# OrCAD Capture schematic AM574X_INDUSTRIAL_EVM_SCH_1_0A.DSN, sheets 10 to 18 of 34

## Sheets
10 Pg23: JTAG Debug: size C
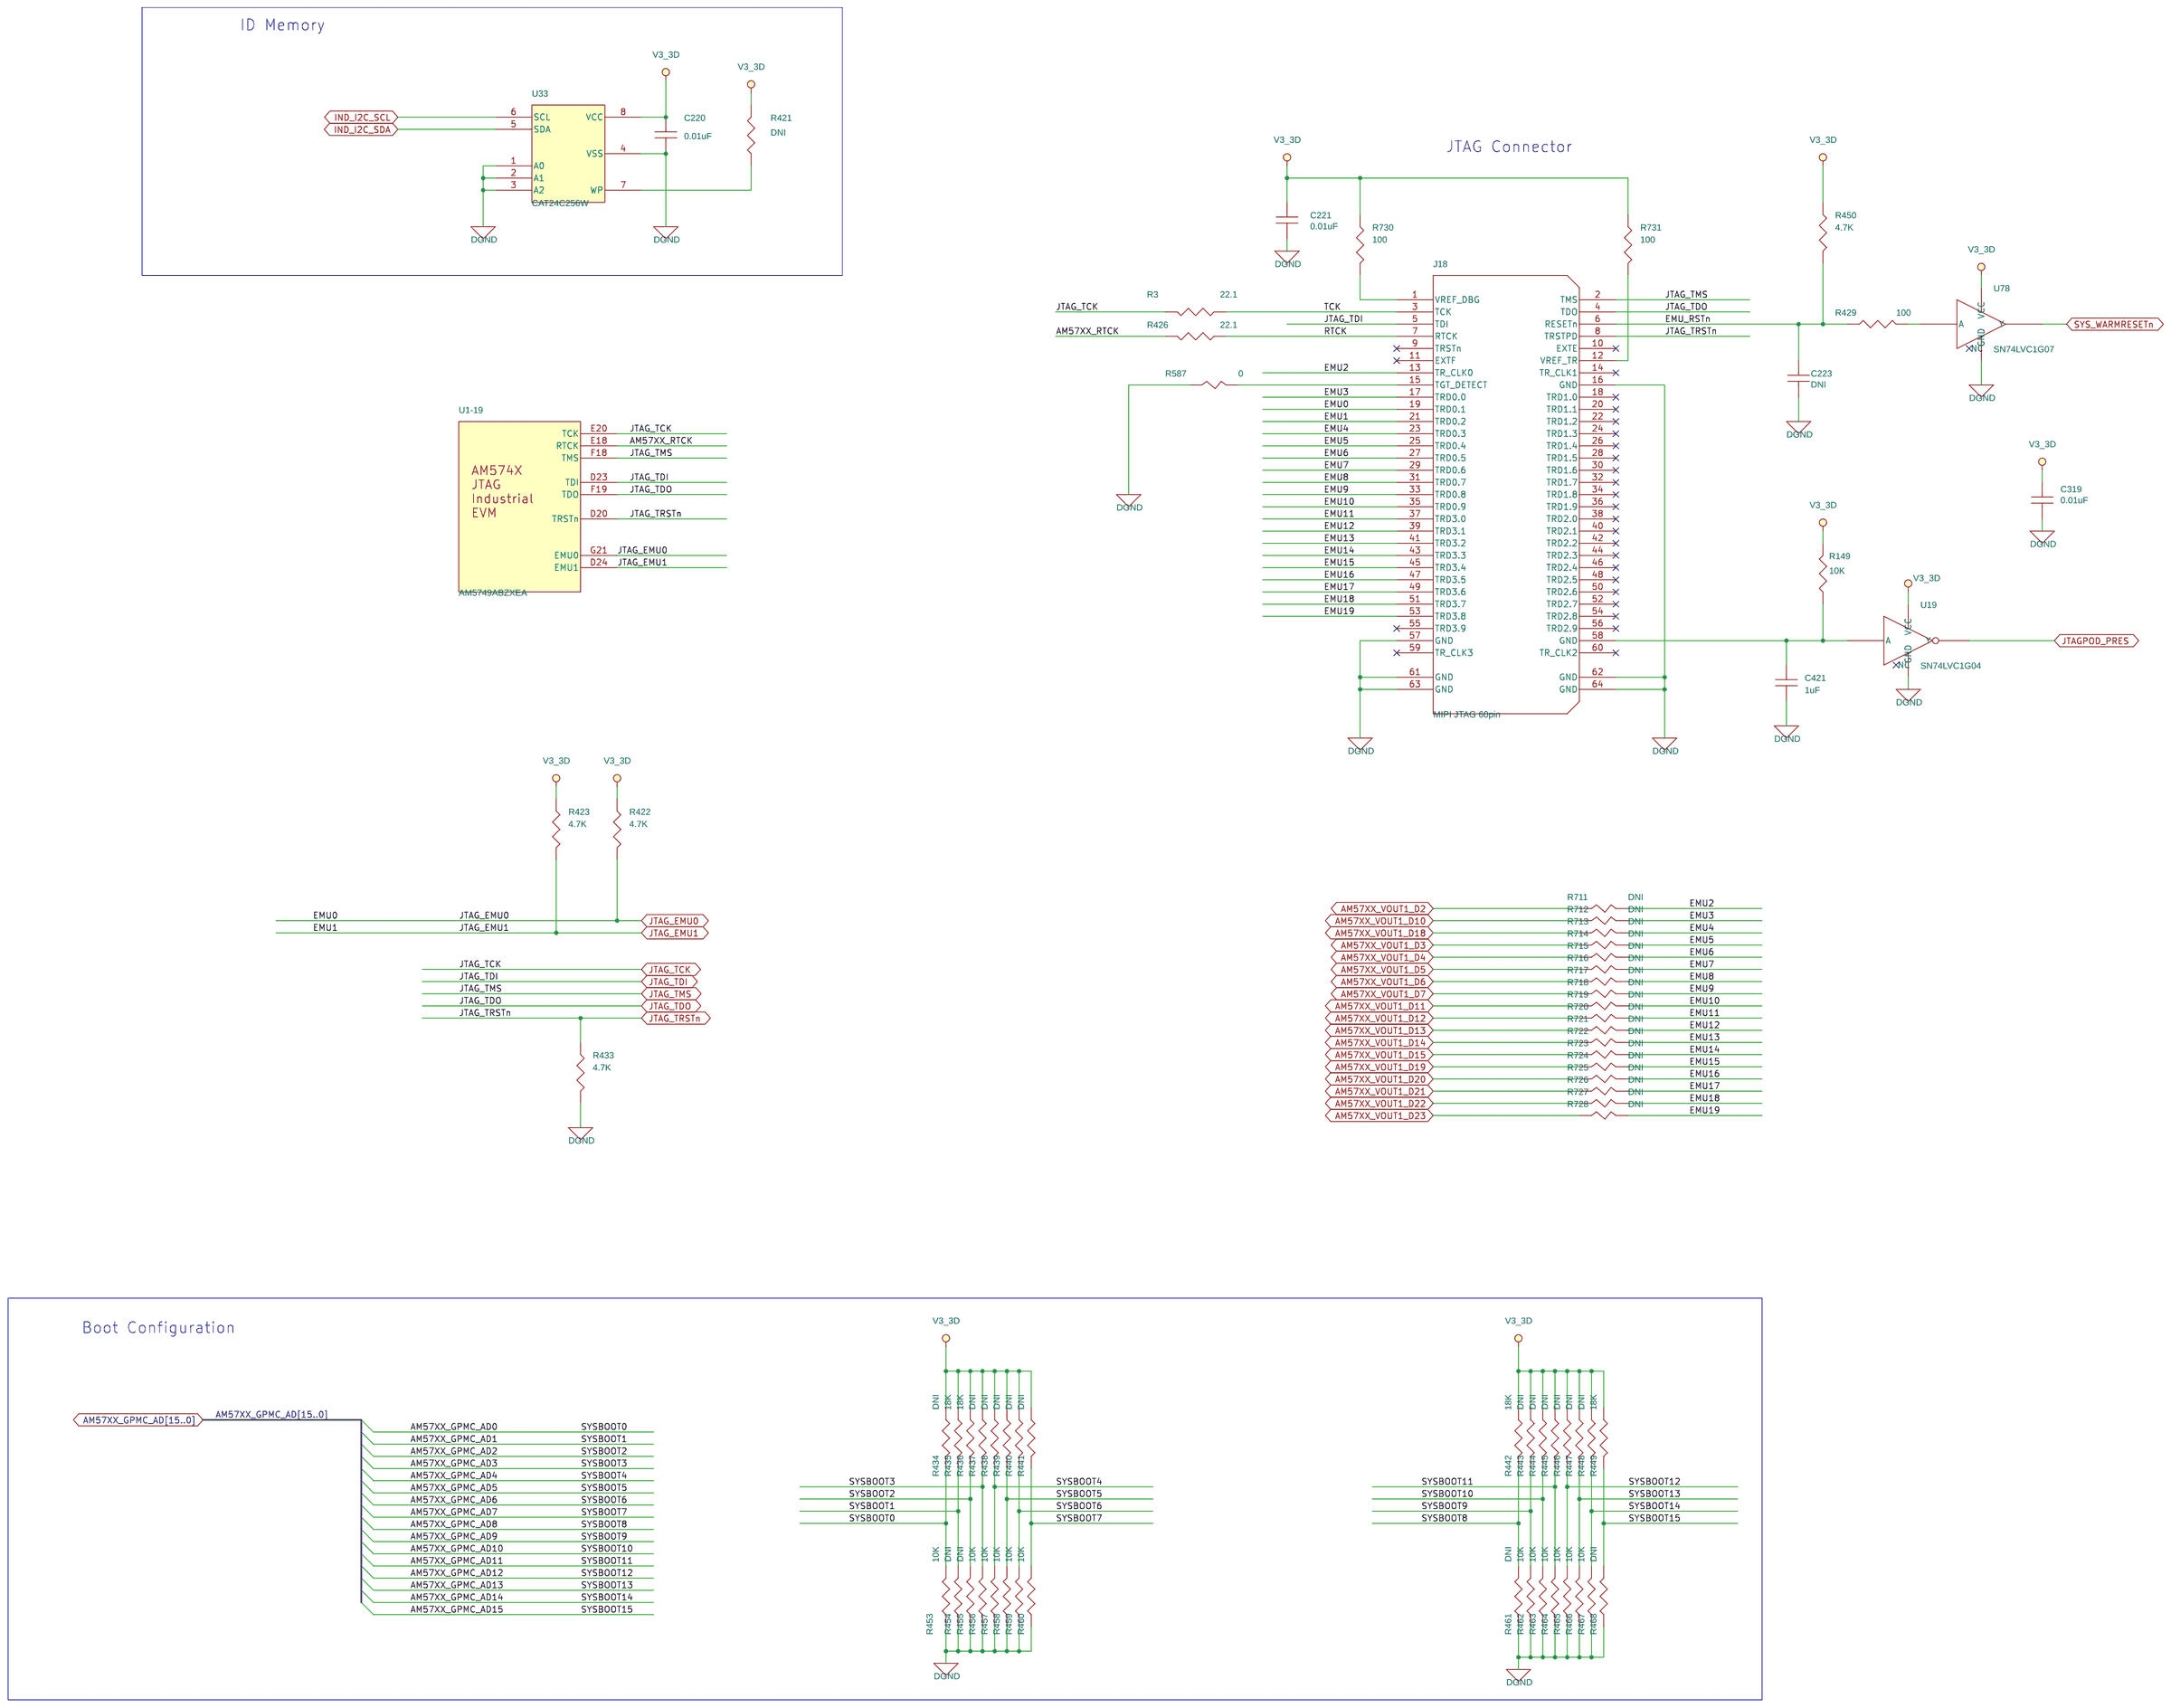
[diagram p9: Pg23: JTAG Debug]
11 Pg16: Camera #1: size C
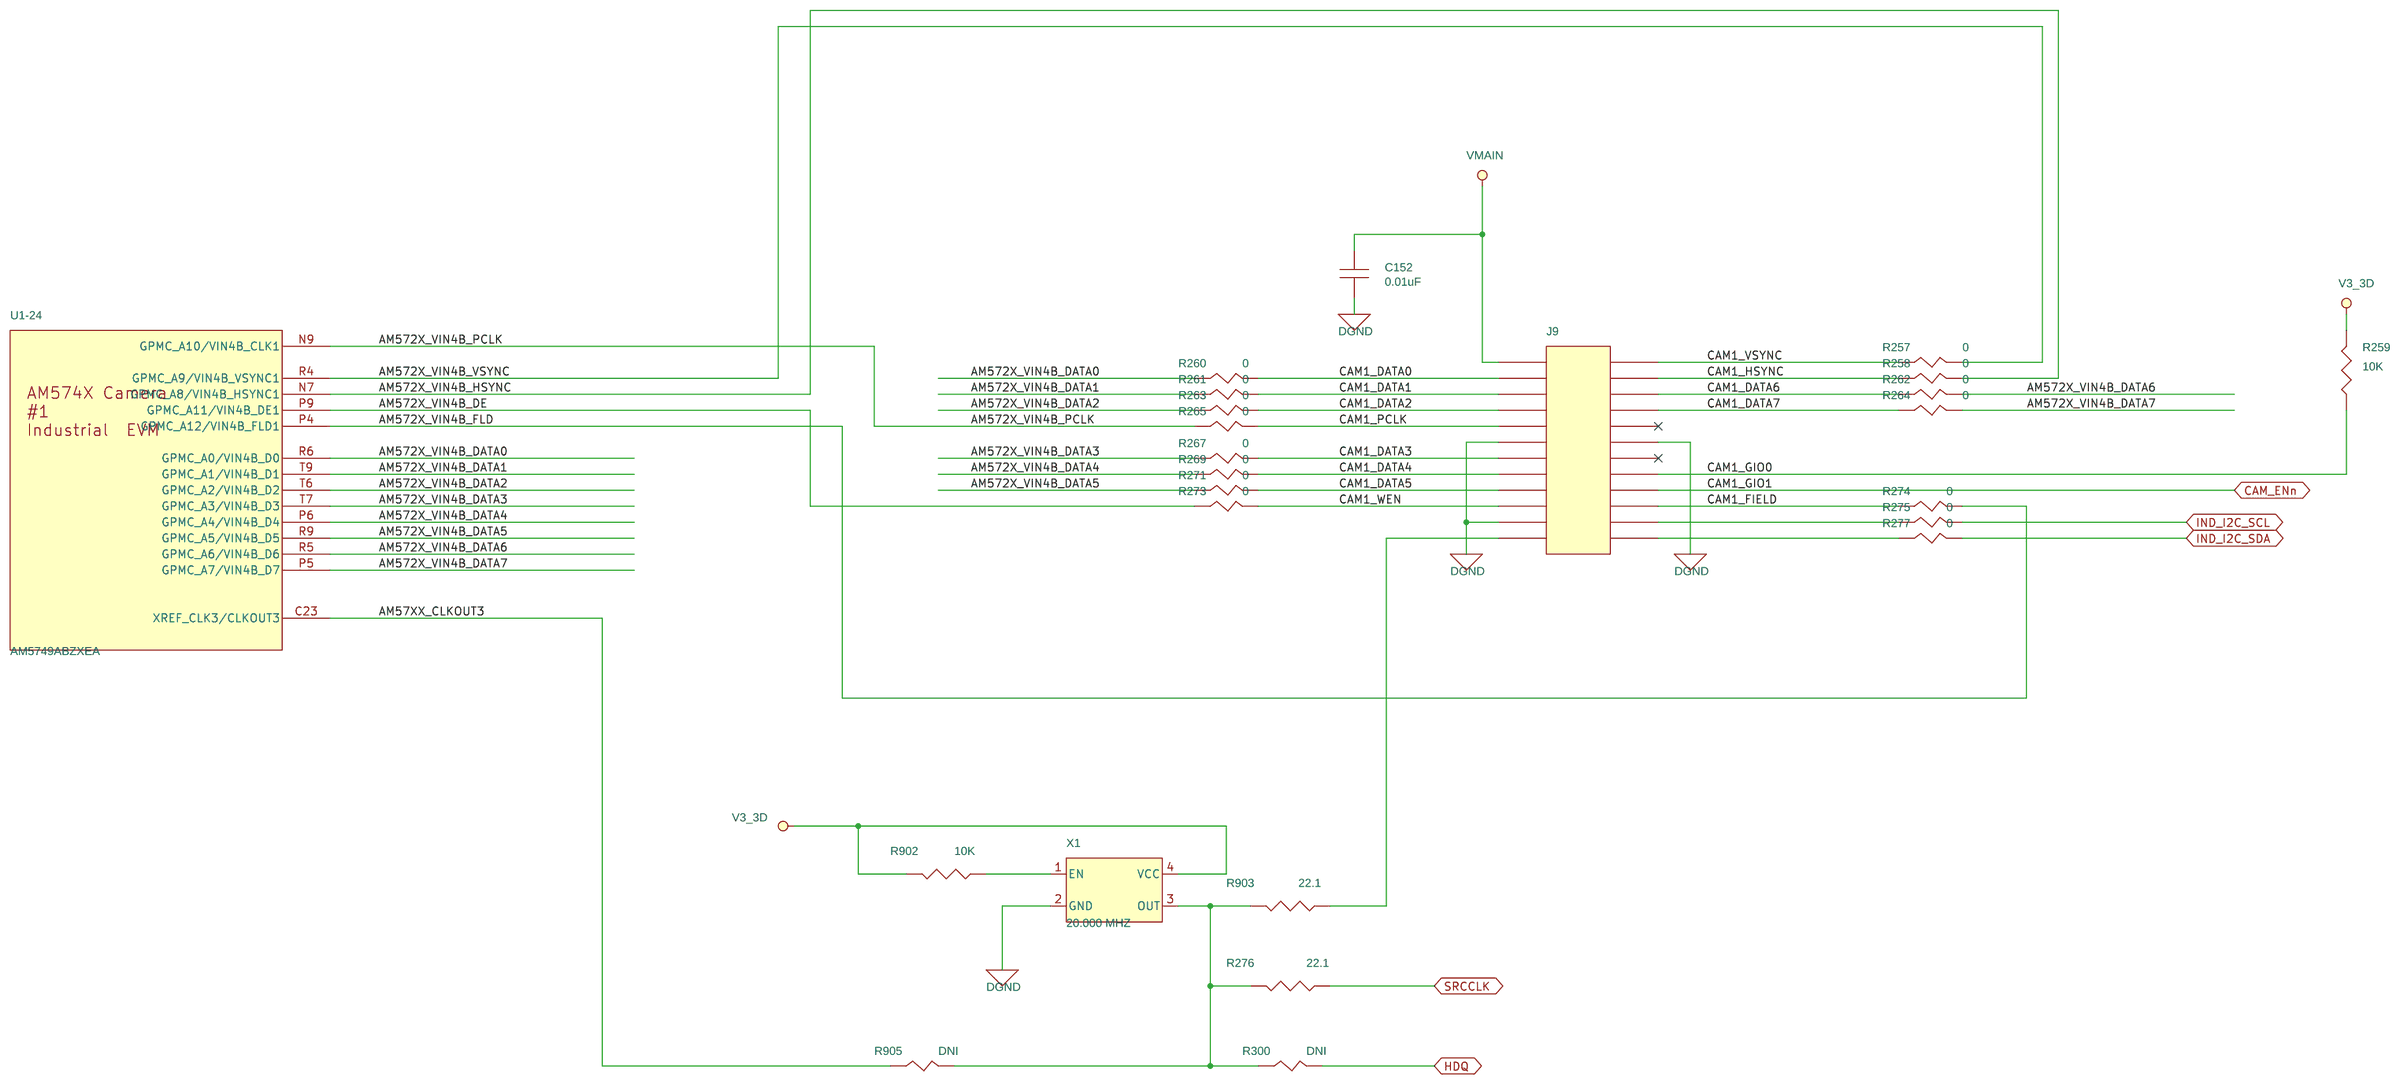
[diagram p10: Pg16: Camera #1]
12 Pg29: Profibus: size C
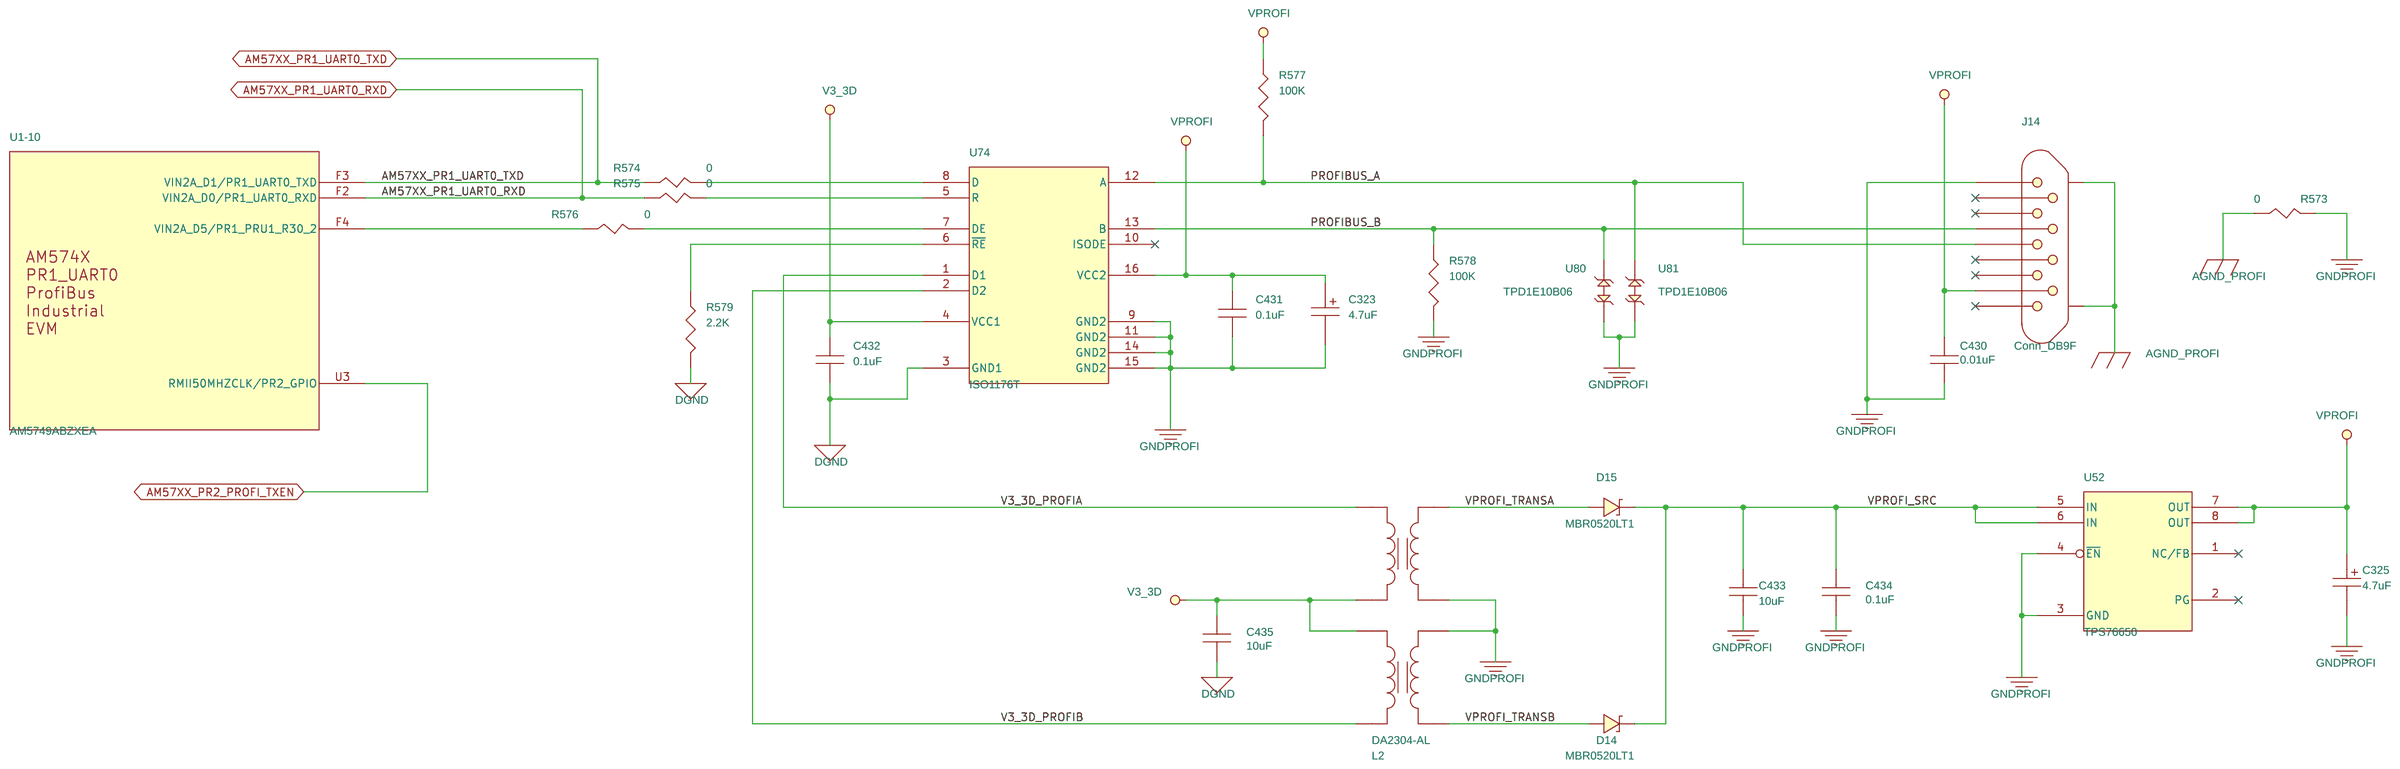
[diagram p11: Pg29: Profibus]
13 Pg01: Title Page
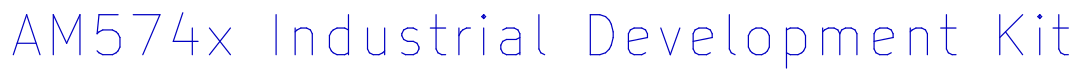
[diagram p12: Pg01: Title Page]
14 Pg27: USB #2 2.0: size C
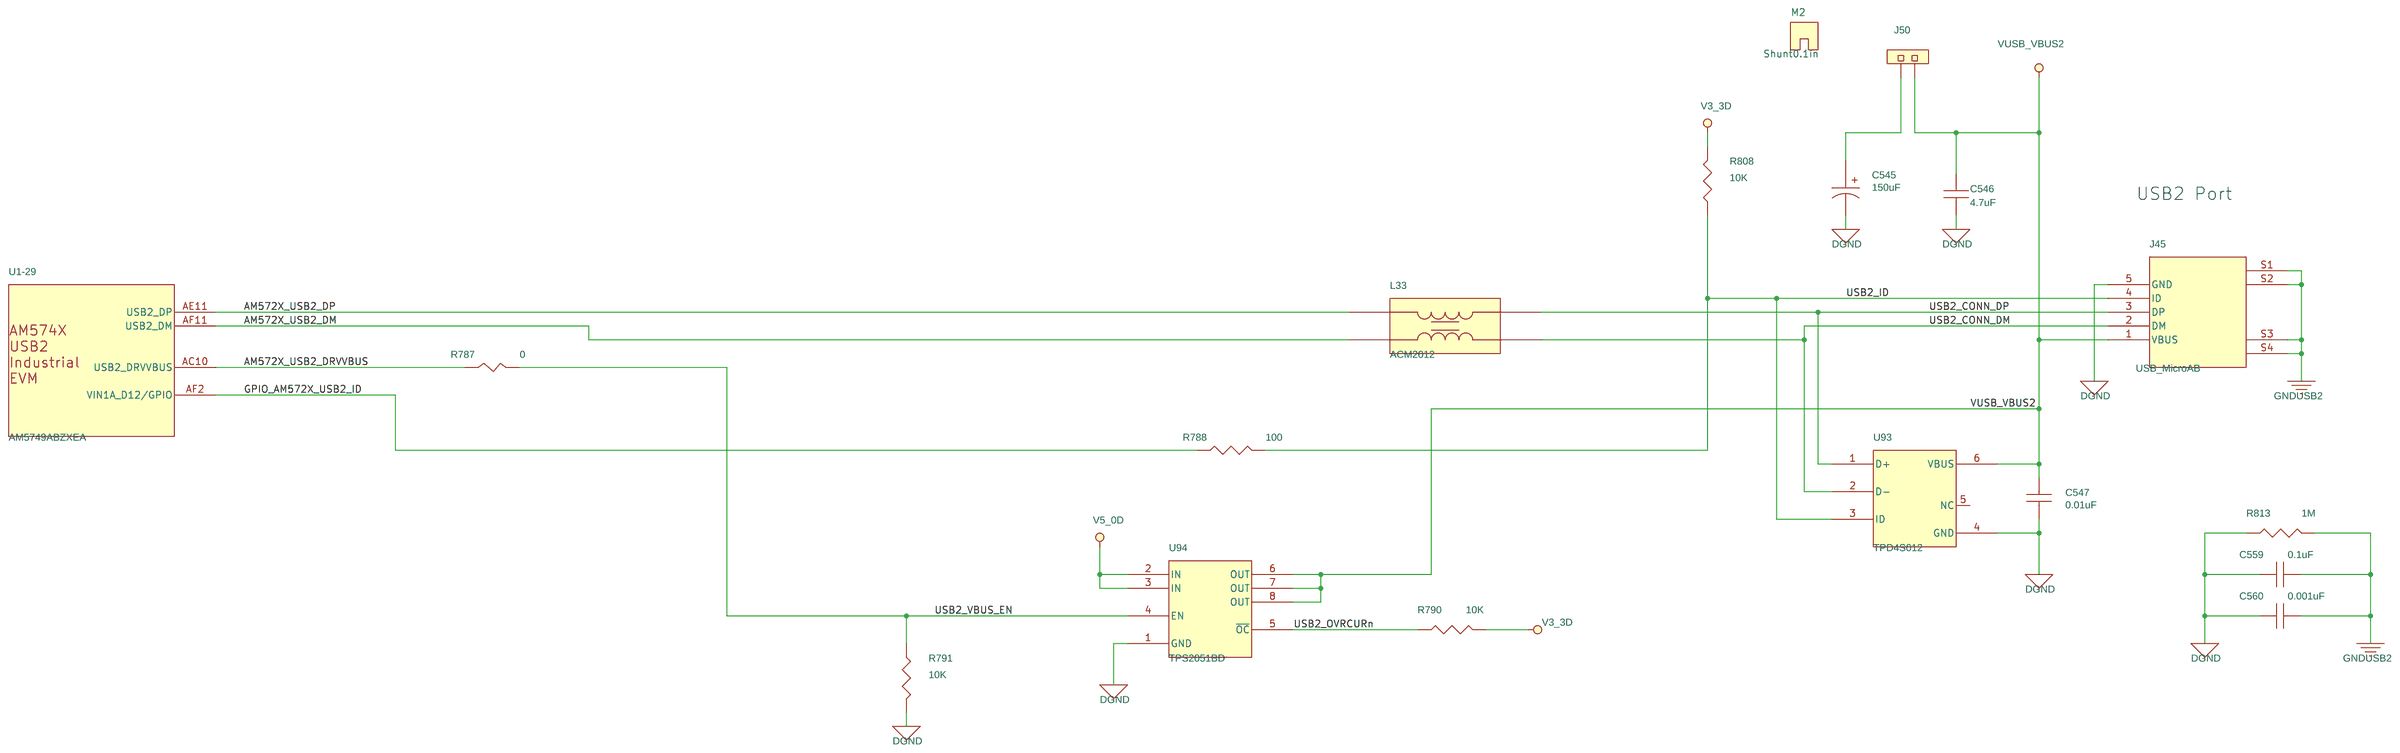
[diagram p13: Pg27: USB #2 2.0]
15 Pg26: USB #1 3.0: size C
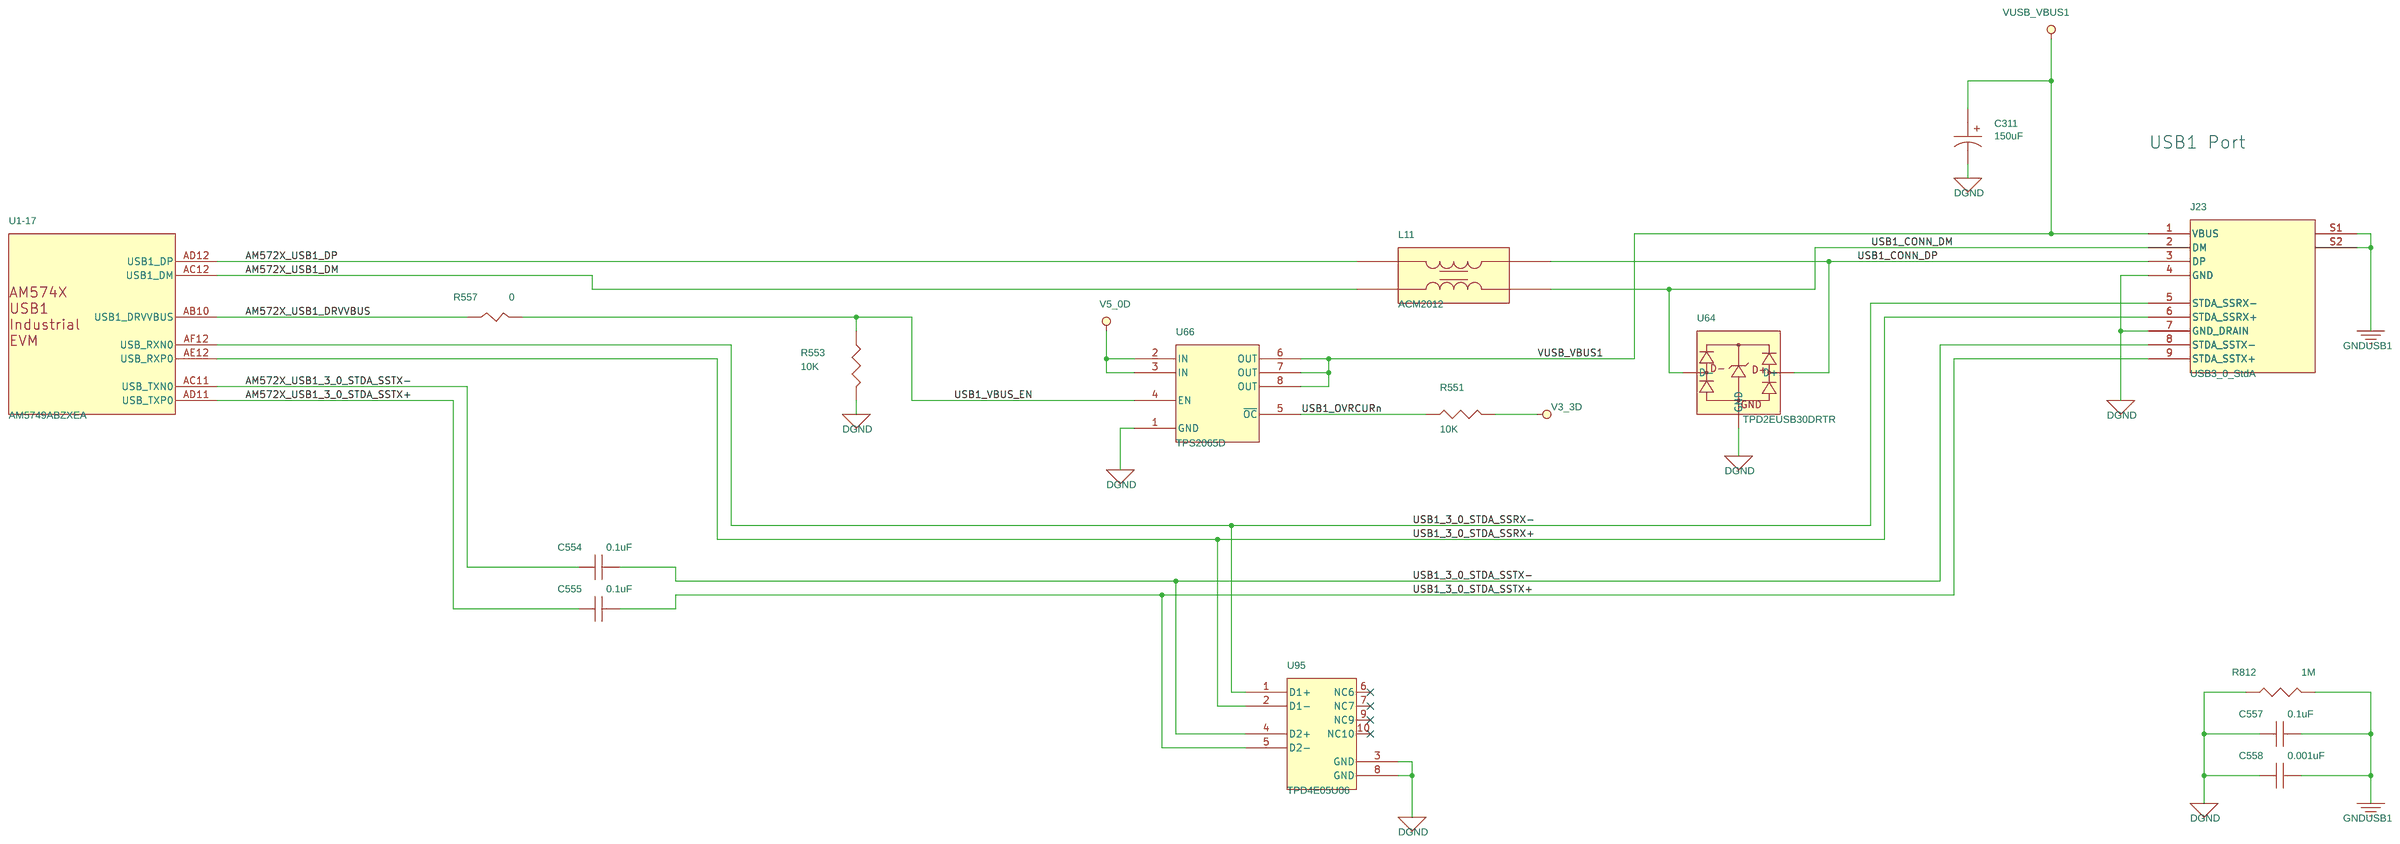
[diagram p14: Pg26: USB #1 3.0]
16 Pg08: DDR3 Memory 1: size C
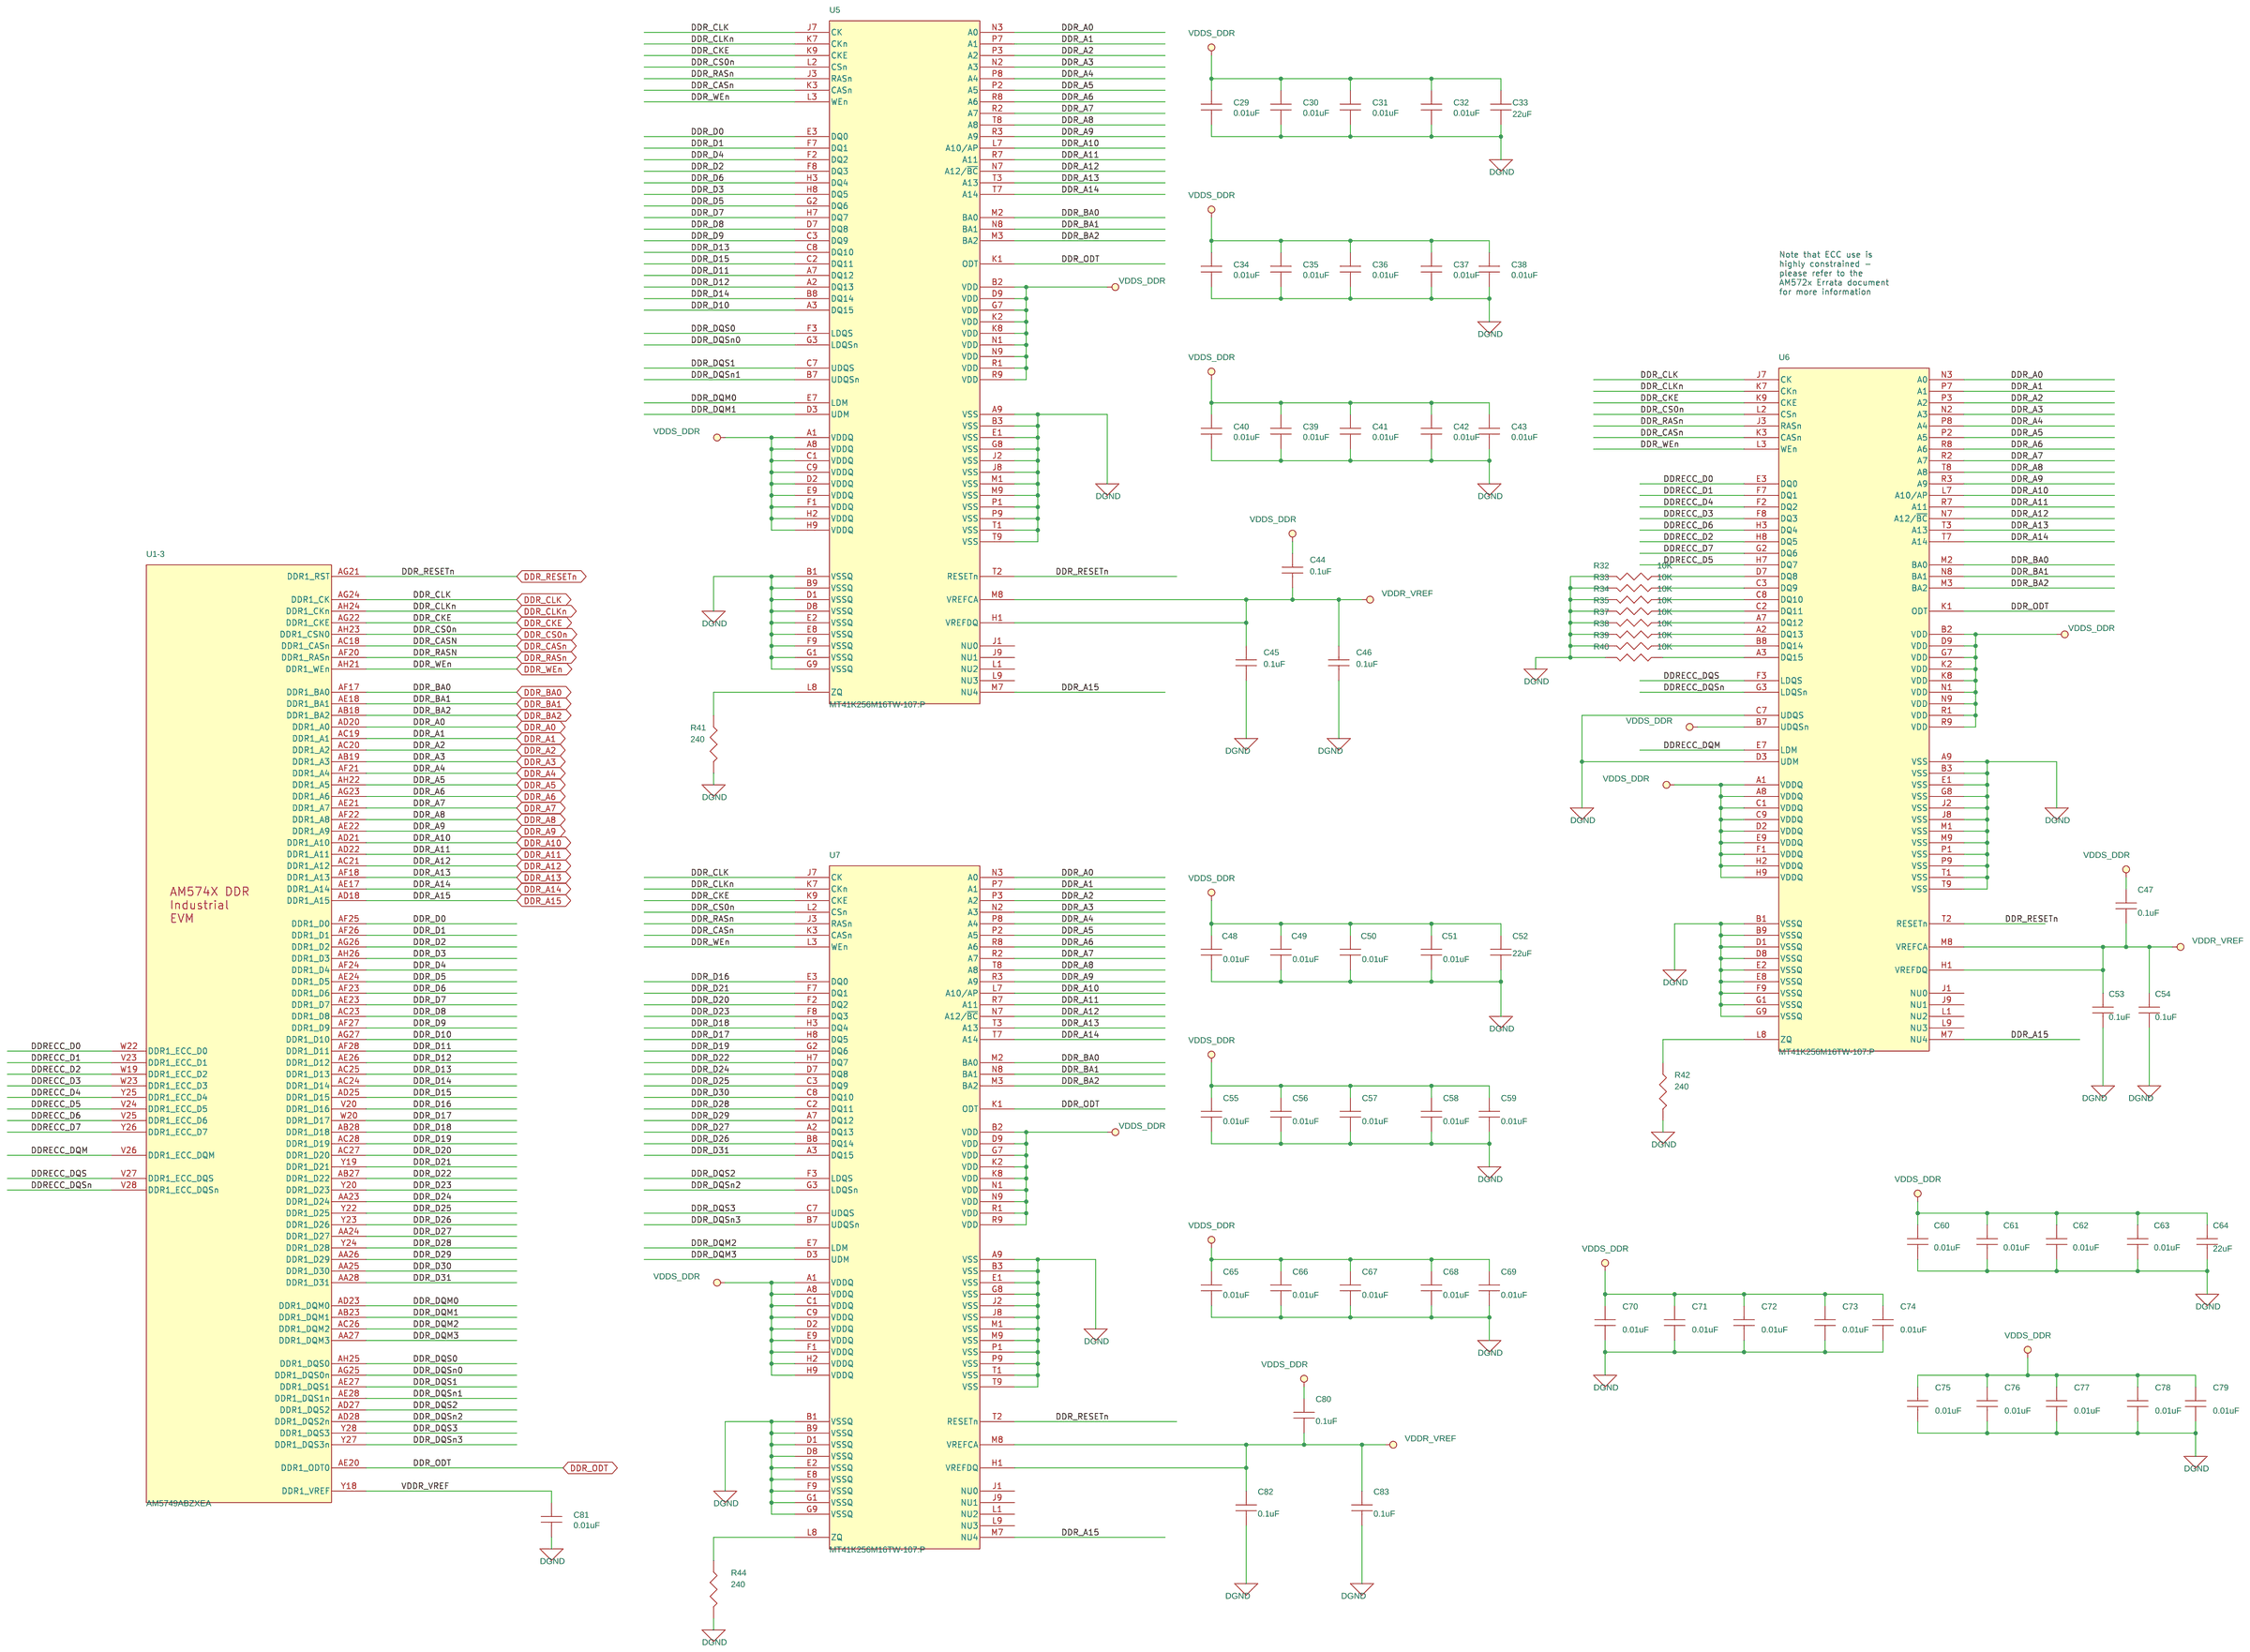
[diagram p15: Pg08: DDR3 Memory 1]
17 Pg13: ICSS2 Ethernet 0: size C
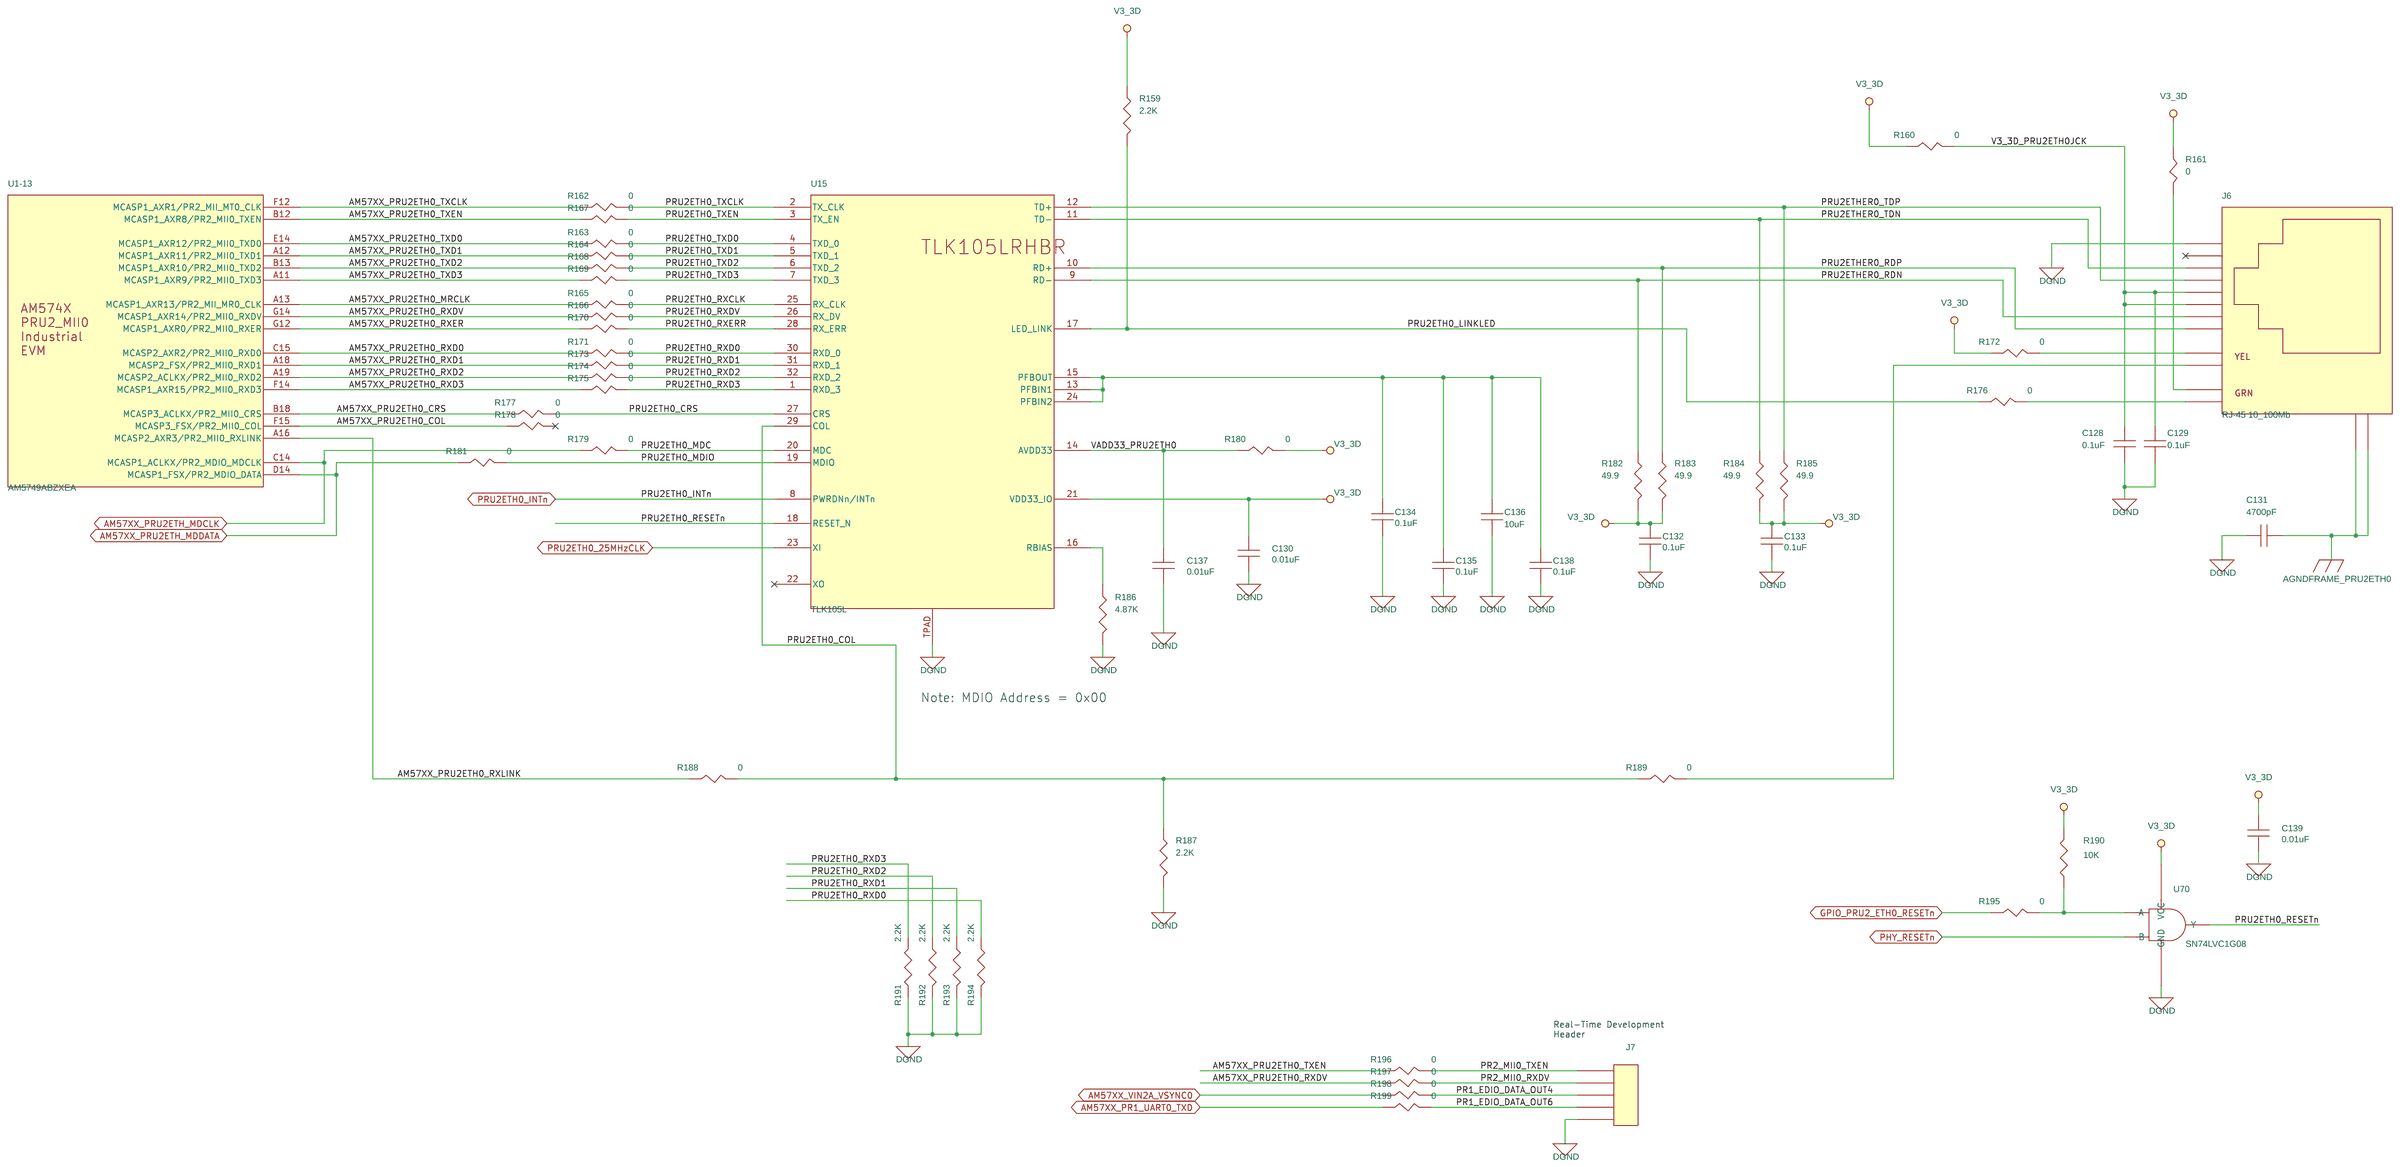
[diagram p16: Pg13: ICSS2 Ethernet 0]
18 Pg31: PCIE Connector: size C
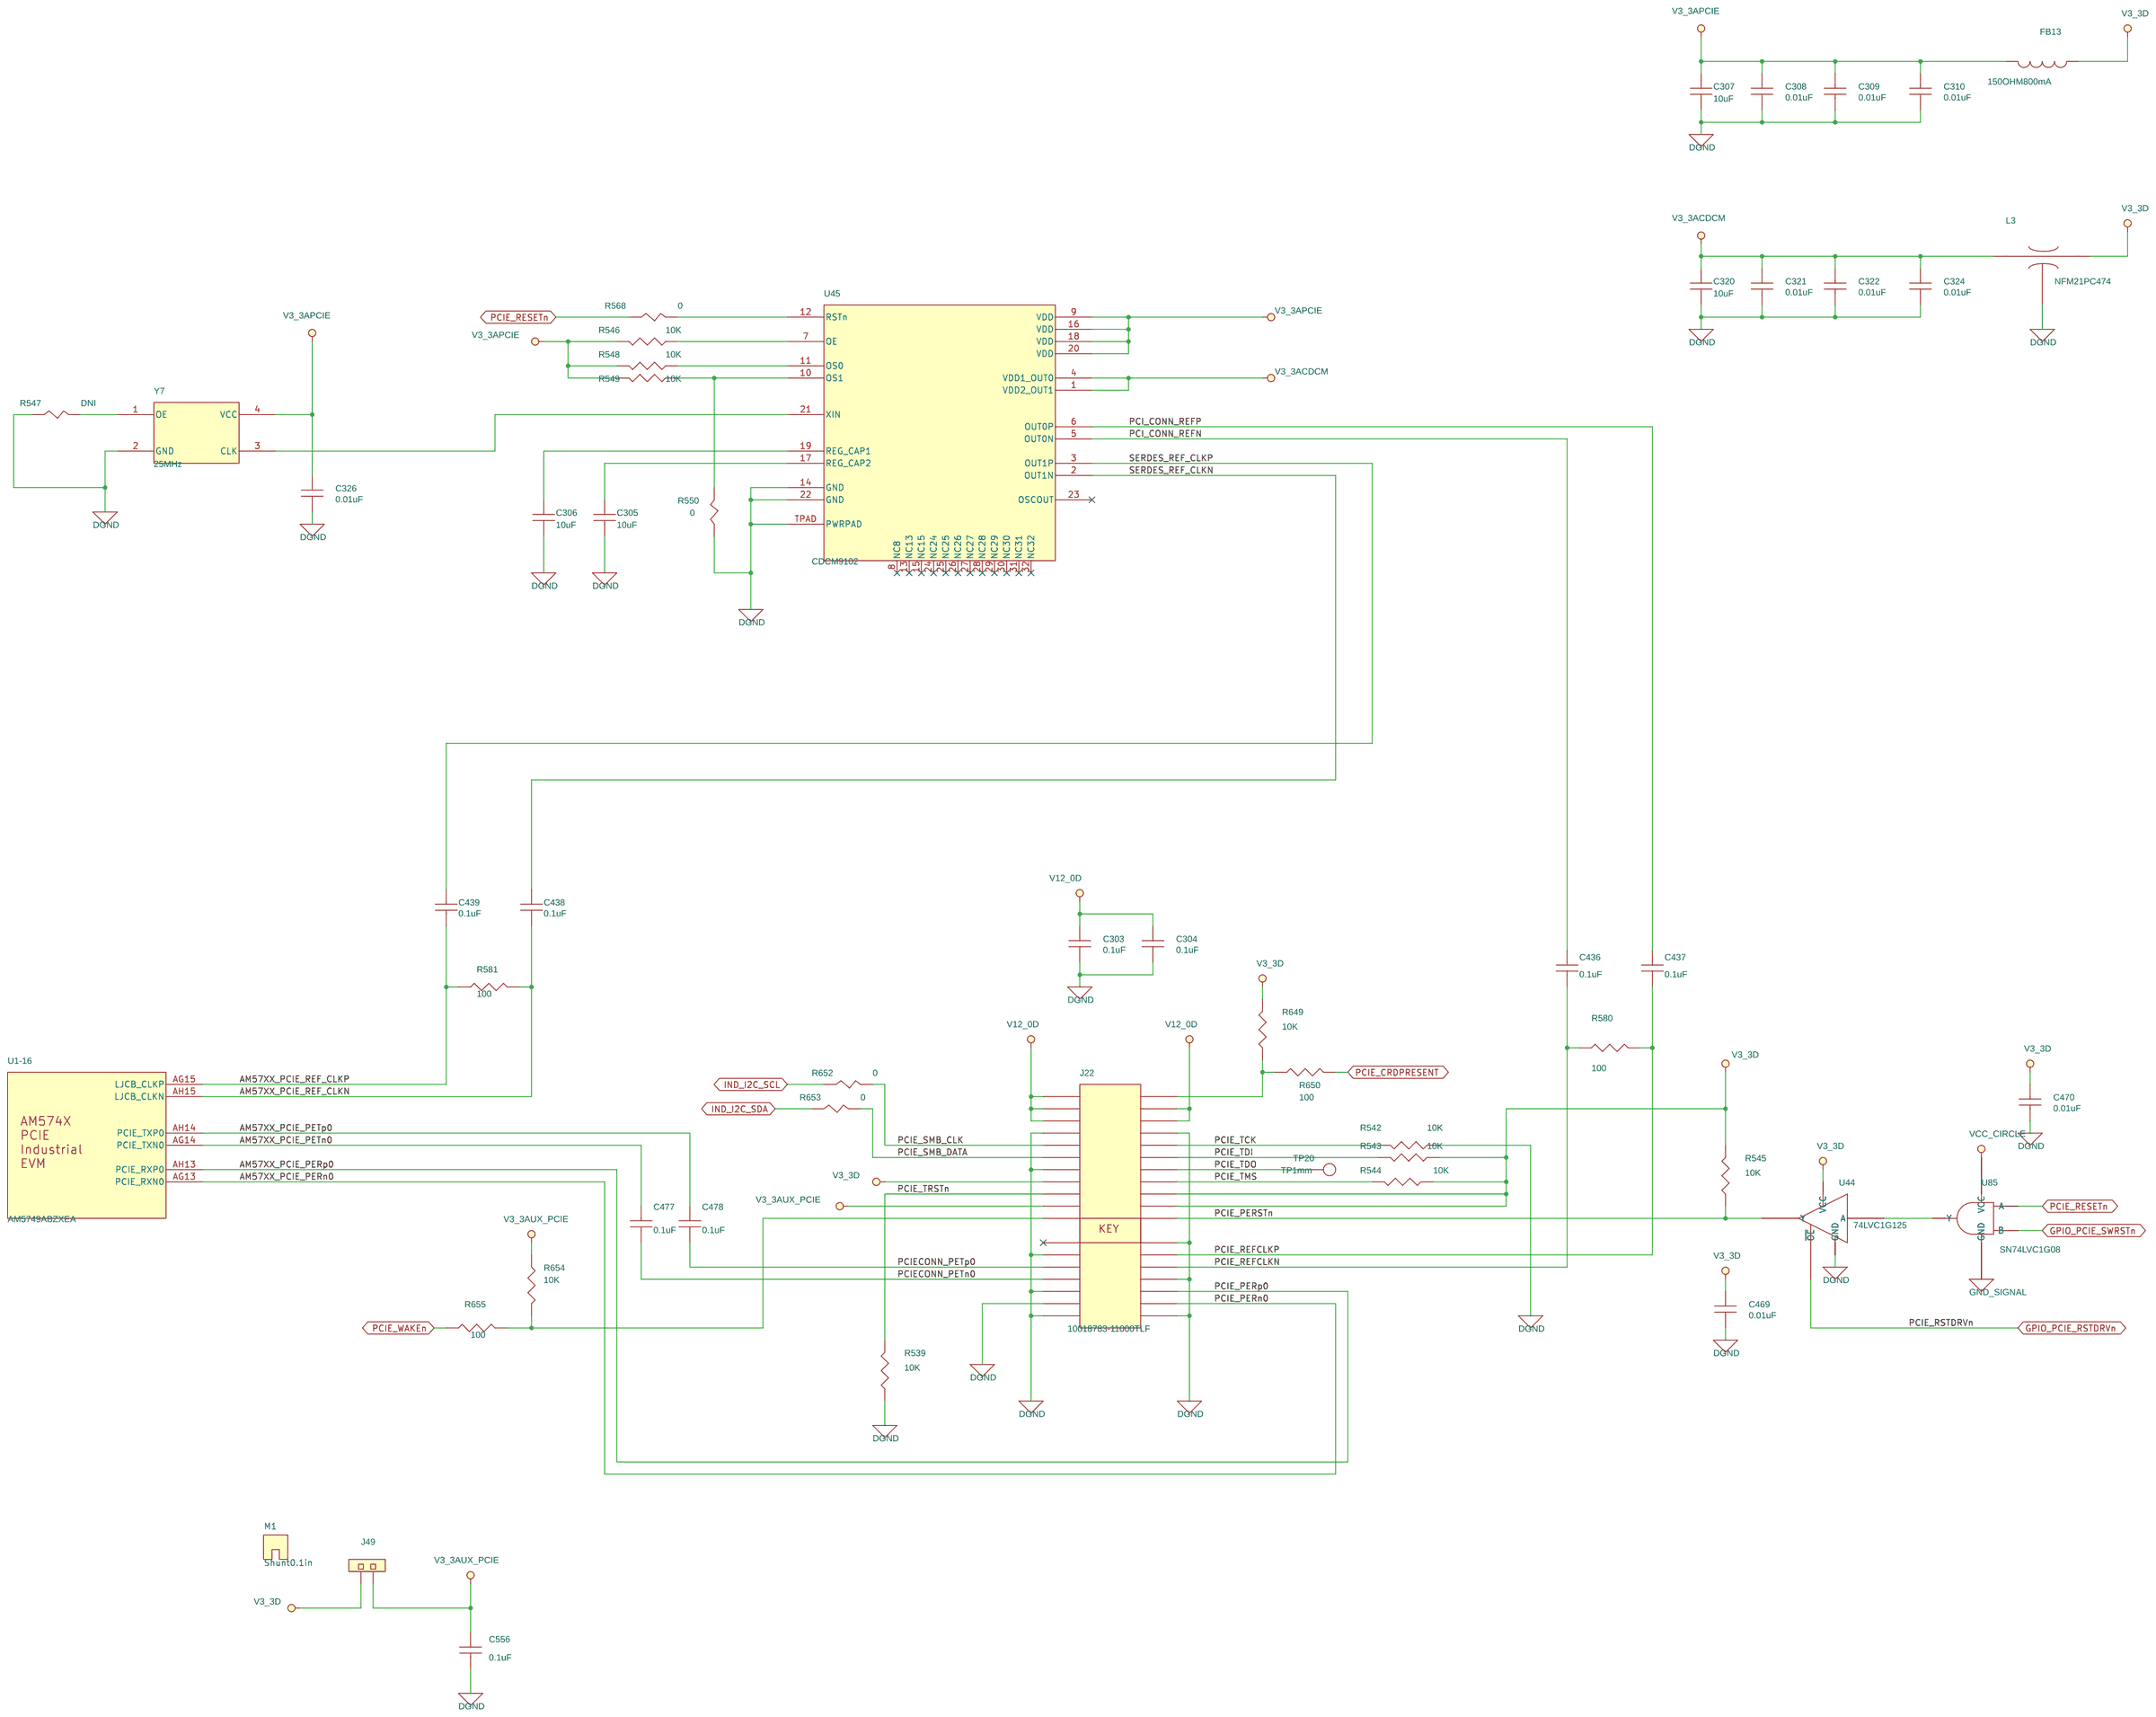
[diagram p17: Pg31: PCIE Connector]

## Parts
sheet Pg08: DDR3 Memory 1
C29  0.01uF  [SM-7351-CAP-0402]
C30  0.01uF  [SM-7351-CAP-0402]
C31  0.01uF  [SM-7351-CAP-0402]
C32  0.01uF  [SM-7351-CAP-0402]
C33  22uF  [SM-7351-CAP-0805]
C34  0.01uF  [SM-7351-CAP-0402]
C35  0.01uF  [SM-7351-CAP-0402]
C36  0.01uF  [SM-7351-CAP-0402]
C37  0.01uF  [SM-7351-CAP-0402]
C38  0.01uF  [SM-7351-CAP-0402]
C39  0.01uF  [SM-7351-CAP-0402]
C40  0.01uF  [SM-7351-CAP-0402]
C41  0.01uF  [SM-7351-CAP-0402]
C42  0.01uF  [SM-7351-CAP-0402]
C43  0.01uF  [SM-7351-CAP-0402]
C44  0.1uF  [SM-7351-CAP-0402]
C45  0.1uF  [SM-7351-CAP-0402]
C46  0.1uF  [SM-7351-CAP-0402]
C47  0.1uF  [SM-7351-CAP-0402]
C48  0.01uF  [SM-7351-CAP-0402]
C49  0.01uF  [SM-7351-CAP-0402]
C50  0.01uF  [SM-7351-CAP-0402]
C51  0.01uF  [SM-7351-CAP-0402]
C52  22uF  [SM-7351-CAP-0805]
C53  0.1uF  [SM-7351-CAP-0402]
C54  0.1uF  [SM-7351-CAP-0402]
C55  0.01uF  [SM-7351-CAP-0402]
C56  0.01uF  [SM-7351-CAP-0402]
C57  0.01uF  [SM-7351-CAP-0402]
C58  0.01uF  [SM-7351-CAP-0402]
C59  0.01uF  [SM-7351-CAP-0402]
C60  0.01uF  [SM-7351-CAP-0402]
C61  0.01uF  [SM-7351-CAP-0402]
C62  0.01uF  [SM-7351-CAP-0402]
C63  0.01uF  [SM-7351-CAP-0402]
C64  22uF  [SM-7351-CAP-0805]
C65  0.01uF  [SM-7351-CAP-0402]
C66  0.01uF  [SM-7351-CAP-0402]
C67  0.01uF  [SM-7351-CAP-0402]
C68  0.01uF  [SM-7351-CAP-0402]
C69  0.01uF  [SM-7351-CAP-0402]
C70  0.01uF  [SM-7351-CAP-0402]
C71  0.01uF  [SM-7351-CAP-0402]
C72  0.01uF  [SM-7351-CAP-0402]
C73  0.01uF  [SM-7351-CAP-0402]
C74  0.01uF  [SM-7351-CAP-0402]
C75  0.01uF  [SM-7351-CAP-0402]
C76  0.01uF  [SM-7351-CAP-0402]
C77  0.01uF  [SM-7351-CAP-0402]
C78  0.01uF  [SM-7351-CAP-0402]
C79  0.01uF  [SM-7351-CAP-0402]
C80  0.1uF  [SM-7351-CAP-0402]
C81  0.01uF  [SM-7351-CAP-0402]
C82  0.1uF  [SM-7351-CAP-0402]
C83  0.1uF  [SM-7351-CAP-0402]
R32  10K  [SM-7351-RES-0402]
R33  10K  [SM-7351-RES-0402]
R34  10K  [SM-7351-RES-0402]
R35  10K  [SM-7351-RES-0402]
R37  10K  [SM-7351-RES-0402]
R38  10K  [SM-7351-RES-0402]
R39  10K  [SM-7351-RES-0402]
R40  10K  [SM-7351-RES-0402]
R41  240  [sm-7351-res-0402]
R42  240  [sm-7351-res-0402]
R44  240  [sm-7351-res-0402]
U5  MT41K256M16TW-107:P  [bga9x14-96]
U6  MT41K256M16TW-107:P  [bga9x14-96]
U7  MT41K256M16TW-107:P  [bga9x14-96]
sheet Pg13: ICSS2 Ethernet 0
C128  0.1uF  [SM-7351-CAP-0402]
C129  0.1uF  [SM-7351-CAP-0402]
C130  0.01uF  [SM-7351-CAP-0402]
C131  4700pF  [SM-7351-CAP-0402]
C132  0.1uF  [SM-7351-CAP-0402]
C133  0.1uF  [SM-7351-CAP-0402]
C134  0.1uF  [SM-7351-CAP-0402]
C135  0.1uF  [SM-7351-CAP-0402]
C136  10uF  [SM-7351-CAP-0805]
C137  0.01uF  [SM-7351-CAP-0402]
C138  0.1uF  [SM-7351-CAP-0402]
C139  0.01uF  [SM-7351-CAP-0402]
J6  RJ-45 10_100Mb  [CNRJ45-1X1WLED]
J7  HEADER 5  [HEADER_5X1]
R159  2.2K  [sm-7351-res-0402]
R160  0  [SM-7351-RES-0402]
R161  0  [SM-7351-RES-0402]
R162  0  [SM-7351-RES-0402]
R163  0  [SM-7351-RES-0402]
R164  0  [SM-7351-RES-0402]
R165  0  [SM-7351-RES-0402]
R166  0  [SM-7351-RES-0402]
R167  0  [SM-7351-RES-0402]
R168  0  [SM-7351-RES-0402]
R169  0  [SM-7351-RES-0402]
R170  0  [SM-7351-RES-0402]
R171  0  [SM-7351-RES-0402]
R172  0  [SM-7351-RES-0402]
R173  0  [SM-7351-RES-0402]
R174  0  [SM-7351-RES-0402]
R175  0  [SM-7351-RES-0402]
R176  0  [SM-7351-RES-0402]
R177  0  [SM-7351-RES-0402]
R178  0  [SM-7351-RES-0402]
R179  0  [SM-7351-RES-0402]
R180  0  [SM-7351-RES-0603]
R181  0  [SM-7351-RES-0402]
R182  49.9  [SM-7351-RES-0402]
R183  49.9  [SM-7351-RES-0402]
R184  49.9  [SM-7351-RES-0402]
R185  49.9  [SM-7351-RES-0402]
R186  4.87K  [SM-7351-RES-0402]
R187  2.2K  [sm-7351-res-0402]
R188  0  [SM-7351-RES-0402]
R189  0  [SM-7351-RES-0402]
R190  10K  [SM-7351-RES-0402]
R191  2.2K  [sm-7351-res-0402]
R192  2.2K  [sm-7351-res-0402]
R193  2.2K  [sm-7351-res-0402]
R194  2.2K  [sm-7351-res-0402]
R195  0  [SM-7351-RES-0402]
R196  0  [SM-7351-RES-0402]
R197  0  [SM-7351-RES-0402]
R198  0  [SM-7351-RES-0402]
R199  0  [SM-7351-RES-0402]
U15  TLK105L  [qfn5x5-32-39m]
U70  SN74LVC1G08  [sm-so-sc70-5]
sheet Pg16: Camera #1
C152  0.01uF  [SM-7351-CAP-0402]
J9  HEADER 12x2  [hdr2x12]
R257  0  [SM-7351-RES-0402]
R258  0  [SM-7351-RES-0402]
R259  10K  [SM-7351-RES-0402]
R260  0  [SM-7351-RES-0402]
R261  0  [SM-7351-RES-0402]
R262  0  [SM-7351-RES-0402]
R263  0  [SM-7351-RES-0402]
R264  0  [SM-7351-RES-0402]
R265  0  [SM-7351-RES-0402]
R267  0  [SM-7351-RES-0402]
R269  0  [SM-7351-RES-0402]
R271  0  [SM-7351-RES-0402]
R273  0  [SM-7351-RES-0402]
R274  0  [SM-7351-RES-0402]
R275  0  [SM-7351-RES-0402]
R276  22.1  [SM-7351-RES-0402]
R277  0  [SM-7351-RES-0402]
R300  DNI  [SM-7351-RES-0402]
R902  10K  [SM-7351-RES-0402]
R903  22.1  [SM-7351-RES-0402]
R905  DNI  [SM-7351-RES-0402]
X1  20.000 MHZ  [OSC7X5-71M]
sheet Pg23: JTAG Debug
C220  0.01uF  [SM-7351-CAP-0402]
C221  0.01uF  [SM-7351-CAP-0402]
C223  DNI  [SM-7351-CAP-0402]
C319  0.01uF  [SM-7351-CAP-0402]
C421  1uF  [SM-7351-CAP-0603]
J18  MIPI JTAG 60pin  [CNQSH030DA]
R3  22.1  [SM-7351-RES-0402]
R149  10K  [SM-7351-RES-0402]
R421  DNI  [SM-7351-RES-0402]
R422  4.7K  [SM-7351-RES-0402]
R423  4.7K  [SM-7351-RES-0402]
R426  22.1  [SM-7351-RES-0402]
R429  100  [SM-7351-RES-0402]
R433  4.7K  [SM-7351-RES-0402]
R434  DNI  [SM-7351-RES-0402]
R435  18K  [SM-7351-RES-0402]
R436  18K  [SM-7351-RES-0402]
R437  DNI  [SM-7351-RES-0402]
R438  DNI  [SM-7351-RES-0402]
R439  DNI  [SM-7351-RES-0402]
R440  DNI  [SM-7351-RES-0402]
R441  DNI  [SM-7351-RES-0402]
R442  18K  [SM-7351-RES-0402]
R443  DNI  [SM-7351-RES-0402]
R444  DNI  [SM-7351-RES-0402]
R445  DNI  [SM-7351-RES-0402]
R446  DNI  [SM-7351-RES-0402]
R447  DNI  [SM-7351-RES-0402]
R448  DNI  [SM-7351-RES-0402]
R449  18K  [SM-7351-RES-0402]
R450  4.7K  [SM-7351-RES-0402]
R453  10K  [SM-7351-RES-0402]
R454  DNI  [SM-7351-RES-0402]
R455  DNI  [SM-7351-RES-0402]
R456  10K  [SM-7351-RES-0402]
R457  10K  [SM-7351-RES-0402]
R458  10K  [SM-7351-RES-0402]
R459  10K  [SM-7351-RES-0402]
R460  10K  [SM-7351-RES-0402]
R461  DNI  [SM-7351-RES-0402]
R462  10K  [SM-7351-RES-0402]
R463  10K  [SM-7351-RES-0402]
R464  10K  [SM-7351-RES-0402]
R465  10K  [SM-7351-RES-0402]
R466  10K  [SM-7351-RES-0402]
R467  10K  [SM-7351-RES-0402]
R468  DNI  [SM-7351-RES-0402]
R587  0  [SM-7351-RES-0402]
R711  DNI  [SM-7351-RES-0402]
R712  DNI  [SM-7351-RES-0402]
R713  DNI  [SM-7351-RES-0402]
R714  DNI  [SM-7351-RES-0402]
R715  DNI  [SM-7351-RES-0402]
R716  DNI  [SM-7351-RES-0402]
R717  DNI  [SM-7351-RES-0402]
R718  DNI  [SM-7351-RES-0402]
R719  DNI  [SM-7351-RES-0402]
R720  DNI  [SM-7351-RES-0402]
R721  DNI  [SM-7351-RES-0402]
R722  DNI  [SM-7351-RES-0402]
R723  DNI  [SM-7351-RES-0402]
R724  DNI  [SM-7351-RES-0402]
R725  DNI  [SM-7351-RES-0402]
R726  DNI  [SM-7351-RES-0402]
R727  DNI  [SM-7351-RES-0402]
R728  DNI  [SM-7351-RES-0402]
R730  100  [SM-7351-RES-0402]
R731  100  [SM-7351-RES-0402]
U19  SN74LVC1G04  [SC70-5-43M]
U33  CAT24C256W  [SOIC_8]
U78  SN74LVC1G07  [SC70-5-43M]
sheet Pg26: USB #1 3.0
C311  150uF  [SM-7351-CAP-2917]
C554  0.1uF  [SM-7351-CAP-0402]
C555  0.1uF  [SM-7351-CAP-0402]
C557  0.1uF  [SM-7351-CAP-0402]
C558  0.001uF  [SM-7351-CAP-0402]
J23  USB3_0_StdA  [cn_lpaf3102nl]
L11  ACM2012  [ACM2012H]
R551  10K  [SM-7351-RES-0402]
R553  10K  [SM-7351-RES-0402]
R557  0  [SM-7351-RES-0402]
R812  1M  [SM-7351-RES-0402]
U64  TPD2EUSB30DRTR  [SOT1X1-3-20M]
U66  TPS2065D  [U_8_D]
U95  TPD4E05U06  [USON2X1-10-22M]
sheet Pg27: USB #2 2.0
C545  150uF  [SM-7351-CAP-2917]
C546  4.7uF  [SM-7351-CAP-0603]
C547  0.01uF  [SM-7351-CAP-0402]
C559  0.1uF  [SM-7351-CAP-0402]
C560  0.001uF  [SM-7351-CAP-0402]
J45  USB_MicroAB  [ZX62-AB-5PA]
J50  HEADER 2  [header_2x1]
L33  ACM2012  [ACM2012H]
M2  Shunt0.1in  [none]
R787  0  [SM-7351-RES-0402]
R788  100  [SM-7351-RES-0402]
R790  10K  [SM-7351-RES-0402]
R791  10K  [SM-7351-RES-0402]
R808  10K  [SM-7351-RES-0402]
R813  1M  [SM-7351-RES-0402]
U93  TPD4S012  [U_6_DRY]
U94  TPS2051BD  [U_8_D]
sheet Pg29: Profibus
C323  4.7uF  [sm-7351-cap-0805]
C325  4.7uF  [sm-7351-cap-0805]
C430  0.01uF  [SM-7351-CAP-0402]
C431  0.1uF  [SM-7351-CAP-0402]
C432  0.1uF  [SM-7351-CAP-0402]
C433  10uF  [SM-7351-CAP-0805]
C434  0.1uF  [SM-7351-CAP-0402]
C435  10uF  [SM-7351-CAP-1206]
D14  MBR0520LT1  [mbr0520L]
D15  MBR0520LT1  [mbr0520L]
J14  Conn_DB9F  [NorComp_db9F_SMD]
L2  DA2304-AL  [DA2304]
R573  0  [SM-7351-RES-0402]
R574  0  [SM-7351-RES-0402]
R575  0  [SM-7351-RES-0402]
R576  0  [SM-7351-RES-0402]
R577  100K  [SM-7351-RES-0402]
R578  100K  [SM-7351-RES-0402]
R579  2.2K  [sm-7351-res-0402]
U1  AM5749ABZXEA  [BGA23X23-760-117M]  (sections -1,-10,-11,-12,-13,-14,-15,-16,-17,-18,-19,-2,-20,-21,-22,-23,-24,-25,-26,-27,-28,-29,-3,-4,-5,-6,-7,-8,-9)
U52  TPS76650  [soic_8]
U74  ISO1176T  [u_16_dw]
U80  TPD1E10B06  [tpd1e10b06-2l]
U81  TPD1E10B06  [tpd1e10b06-2l]
sheet Pg31: PCIE Connector
C303  0.1uF  [SM-7351-CAP-0402]
C304  0.1uF  [SM-7351-CAP-0402]
C305  10uF  [SM-7351-CAP-0805]
C306  10uF  [SM-7351-CAP-0805]
C307  10uF  [SM-7351-CAP-0805]
C308  0.01uF  [SM-7351-CAP-0402]
C309  0.01uF  [SM-7351-CAP-0402]
C310  0.01uF  [SM-7351-CAP-0402]
C320  10uF  [SM-7351-CAP-0805]
C321  0.01uF  [SM-7351-CAP-0402]
C322  0.01uF  [SM-7351-CAP-0402]
C324  0.01uF  [SM-7351-CAP-0402]
C326  0.01uF  [SM-7351-CAP-0402]
C436  0.1uF  [SM-7351-CAP-0402]
C437  0.1uF  [SM-7351-CAP-0402]
C438  0.1uF  [SM-7351-CAP-0402]
C439  0.1uF  [SM-7351-CAP-0402]
C469  0.01uF  [SM-7351-CAP-0402]
C470  0.01uF  [SM-7351-CAP-0402]
C477  0.1uF  [SM-7351-CAP-0402]
C478  0.1uF  [SM-7351-CAP-0402]
C556  0.1uF  [SM-7351-CAP-0402]
FB13  150OHM800mA  [sm-7351-ind-0805]
J22  10018783-11000TLF  [CN_10018783-11000TLF]
J49  HEADER 2  [header_2x1]
L3  NFM21PC474  [FILT-NFM21PC]
M1  Shunt0.1in  [none]
R539  10K  [SM-7351-RES-0402]
R542  10K  [SM-7351-RES-0402]
R543  10K  [SM-7351-RES-0402]
R544  10K  [SM-7351-RES-0402]
R545  10K  [SM-7351-RES-0402]
R546  10K  [SM-7351-RES-0402]
R547  DNI  [SM-7351-RES-0402]
R548  10K  [SM-7351-RES-0402]
R549  10K  [SM-7351-RES-0402]
R550  0  [SM-7351-RES-0402]
R568  0  [SM-7351-RES-0402]
R580  100  [SM-7351-RES-0402]
R581  100  [SM-7351-RES-0402]
R649  10K  [SM-7351-RES-0402]
R650  100  [SM-7351-RES-0402]
R652  0  [SM-7351-RES-0402]
R653  0  [SM-7351-RES-0402]
R654  10K  [SM-7351-RES-0402]
R655  100  [SM-7351-RES-0402]
TP20  TP1mm  [tp_smd1mmcircle]
U44  74LVC1G125  [SC70-5-43M]
U45  CDCM9102  [qfn5x5-32ti-39m]
U85  SN74LVC1G08  [sm-so-sc70-5]
Y7  25MHz  [asf_smd3_2x5mm]

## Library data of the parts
C29-C32 C34-C43 C48-C51 C55-C63 C65-C79 C81 C130 C137 C139 C152 C220 C221 C308-C310 C319 C321 C322 C324 C326 C430 C469 C470 C547 = 1C_0.01uFCapacitor16V10%0402
C33 C52 C64 = 1C_22uFCapacitor16V10%0805
C44-C47 C53 C54 C80 C82 C83 C128 C129 C132-C135 C138 C223 C436-C439 C477 C478 C554 C555 C557 C559 = C0402C104J4RACTU: DescriptiveText: CAP, CER, 0.1 uF, 16V, 5%, X7R, 0402; Mfr: KEMET
R32-R35 R37-R40 R149 R190 R259 R421 R453-R468 R539 R542-R546 R548 R549 R551 R553 R649 R654 R790 R791 R808 R902 = RMCF0402FT10K0: DescriptiveText: RES, THICK FILM,10K OHM, 1%, 0.063W, SMT0402; Mfr: STACKPOLE ELECTRONICS
R41 R42 R44 = 1R_240OhmResistor1_16W0402
U5-U7 = MT41K256M16HA-107
C131 = 1C_4700pFCapacitor50V10%0402
C136 C305-C307 C320 C433 = 1C_10uFCapacitor16V10%0805
J6 = 2J_ConnectorRJ45_10_100MbAMDIX
J7 = 2H_Header_5x1
R159 R187 R191-R194 R579 = 1R_2.2KOhmResistor1_16W0402
R160-R179 R181 R188 R189 R195-R199 R257 R258 R260-R265 R267 R269 R271 R273-R275 R277 R300 R547 R550 R557 R568 R573-R576 R587 R652 R653 R711-R728 R787 R905 = 1R_ZeroOhmResistor1_16W0402
R180 = 1R_ZeroOhmResistor1_16W0603
R182-R185 = 1R_49.9OhmResistor1_16W0402
R186 = 1R_4.87Kohm1_16W1%smd0402
U15 = TLK105LRHBR
U70 U85 = SN74LVC1G08DCKR
J9 = 2H_Header12x2
R3 R276 R426 R903 = RMCF0402FT22R1: DescriptiveText: RES, THICK FILM, 22.1 OHM, 1%, 0.063W, SMT0402; Mfr: STACKPOLE ELECTRONICS
X1 = CB3LV-3C-20M0000: DescriptiveText: OSC, XO, 20.000MHZ, HCMOS, TTL, SMD-4P; Mfr: CTS-Frequency Controls
C421 = 1C_1uFCapacitor50V10%0603
J18 = 2C_Conn_JTAGMIPI_60pin
R422 R423 R433 R450 = 1R_4.7KOhmResistor1_16W0402
R429 R580 R581 R650 R655 R788 = 1R_100ohm1_16W1%SMD0402: Cost100: 0.02; DescriptiveText: Resistor 100ohm 1/10W 1% 0402; Mfr: Panasonic; MfrNum: ERJ-2RKF1000X; PartName: 100ohm1/10W1%0402; TIIntPartnumber: 1R0246
R434-R449 = 1R_18KohmResistor1_10W1%smd0402
R730 R731 = 1R_100ohm1_10W1%SMD0402: DescriptiveText: Resistor 100ohm 1/10W 1% 0402; PartName: 100ohm1/10W1%0402
U19 = SN74LVC1G04DCKRE4
U33 = 1A_CAT24C256W
U78 = SN74LVC1G07DCKRE4
C311 C545 = T495D157K010ATE100: DescriptiveText: CAP, TANT, 150UF, 10V, 10%, 7343; Mfr: KEMET
C558 C560 = 1C_0.001uFCapacitor50V5%0402
J23 = 1932258-1
L11 L33 = ACM2012H-900-2P-T05
R812 R813 = 1R_1MOhmResistor1_16W0402
U64 = TPD2EUSB30DRTR: DescriptiveText: 2, 4-CHANNEL ESD SOLUTION FOR SUPER-SPEED (6 GBPS) USB 3.0 INTERFACE; Mfr: TEXAS INSTRUMENTS
U66 = 1A_TPS2065D
U95 = TPD4E05U06DQAR
C546 = 1C_4.7uFCapacitor16V10%0603
J45 = USB
J49 J50 = 2H_Header_0
M1 M2 = 2H_Shunt0.1in
U93 = TPD4S012DRYR
U94 = 1A_TPS2051BD
C323 C325 = 4.7uFCapacitor16V20%Tant
C303 C304 C431 C432 C434 C556 = C1005X7R1H104K050BE: DescriptiveText: CAP, CER, 0.1UF, 50V, 10%, X7R, 0402; Mfr: TDK CORPORATION
C435 = C3216X5R1H106K160AB: DescriptiveText: CAP, CER, 10 UF, 10%, 50V,  X5R, 1206, SMD; Mfr: TDK
D14 D15 = Diode_500mA20V: TIIntPartnumber: _1E0007
J14 = 2C_Conn_DSUB9F
L2 = DA2304-ALB
R577 R578 = 1R_100KOhmResistor1_16W0402
U1 = AM5749ABZXEA: DescriptiveText: Dual Cortex A15 Dual C66X SOC AM574x
U52 = TPS76650
U74 = 1A_ISO1176T
U80 U81 = TPD1E10B06DPYR
FB13 = 1L_FerBead_0
J22 = 2C_PCIEConnector_10018783
L3 = 1L_NFM21PC474_EMIFilter_0
TP20 = 2H_Testpoint_SMD1mmCircle
U44 = SN74LVC1G125DCKR
U45 = CDCM9102RHBT
Y7 = 1Y_Oscillator25MHzSMD

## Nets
AGND_PROFI: J14.10 J14.11 R573.2(P2)
AGNDFRAME_PRU2ETH0: C131.2 J6.SHLD1 J6.SHLD2
DGND: C29.2 C30.2 C31.2 C32.2 C33.2 C34.2 C35.2 C36.2 C37.2 C38.2 C39.2 C40.2 C41.2 C42.2 C43.2 C45.2 C46.2 C48.2 C49.2 C50.2 C51.2 C52.2 C53.2 C54.2 C55.2 C56.2 C57.2 C58.2 C59.2 C60.2 C61.2 C62.2 C63.2 C64.2 C65.2 C66.2 C67.2 C68.2 C69.2 C70.2 C71.2 C72.2 C73.2 C74.2 C75.2 C76.2 C77.2 C78.2 C79.2 C81.2 C82.2 C83.2 C128.2 C129.2 C130.2 C131.1 C132.2 C133.2 C134.2 C135.2 C136.2 C137.2 C138.2 C139.2 C152.2 C220.2 C221.2 C223.2 C303.2 C304.2 C305.2 C306.2 C307.2 C308.2 C309.2 C310.2 C311.2 C319.2 C320.2 C321.2 C322.2 C324.2 C326.2 C421.2 C432.2 C435.2 C469.2 C470.2 C545.2 C546.2 C547.2 C556.2 C557.1 C558.1 C559.1 C560.1 J6.8 J7.5 J9.11 J9.12 J9.21 J18.16(GND) J18.57(GND) J18.61(GND) J18.62(GND) J18.63(GND) J18.64(GND) J22.A4 J22.A12 J22.A15 J22.A18 J22.B4 J22.B7 J22.B13 J22.B16 J22.B17 J22.B18 J23.4(GND) J23.7(GND_DRAIN) J45.5(GND) L3.2(GND) R32.2 R33.2 R34.2 R35.2 R37.2 R38.2 R39.2 R40.2 R41.1(P1) R42.1(P1) R44.1(P1) R186.1(P1) R187.1(P1) R191.1(P1) R192.1(P1) R193.1(P1) R194.1(P1) R433.1(P1) R453.1 R454.1 R455.1 R456.1 R457.1 R458.1 R459.1 R460.1 R461.1 R462.1 R463.1 R464.1 R465.1 R466.1 R467.1 R468.1 R539.1 R542.1 R547.2(P2) R550.2(P2) R553.2 R579.1(P1) R587.2(P2) R791.2 R812.2(P2) R813.2(P2) U5.A9(VSS) U5.B1(VSSQ) U5.B3(VSS) U5.B9(VSSQ) U5.D1(VSSQ) U5.D8(VSSQ) U5.E1(VSS) U5.E2(VSSQ) U5.E8(VSSQ) U5.F9(VSSQ) U5.G1(VSSQ) U5.G8(VSS) U5.G9(VSSQ) U5.J2(VSS) U5.J8(VSS) U5.M1(VSS) U5.M9(VSS) U5.P1(VSS) U5.P9(VSS) U5.T1(VSS) U5.T9(VSS) U6.A9(VSS) U6.B1(VSSQ) U6.B3(VSS) U6.B9(VSSQ) U6.C7(UDQS) U6.D1(VSSQ) U6.D3(UDM) U6.D8(VSSQ) U6.E1(VSS) U6.E2(VSSQ) U6.E8(VSSQ) U6.F9(VSSQ) U6.G1(VSSQ) U6.G8(VSS) U6.G9(VSSQ) U6.J2(VSS) U6.J8(VSS) U6.M1(VSS) U6.M9(VSS) U6.P1(VSS) U6.P9(VSS) U6.T1(VSS) U6.T9(VSS) U7.A9(VSS) U7.B1(VSSQ) U7.B3(VSS) U7.B9(VSSQ) U7.D1(VSSQ) U7.D8(VSSQ) U7.E1(VSS) U7.E2(VSSQ) U7.E8(VSSQ) U7.F9(VSSQ) U7.G1(VSSQ) U7.G8(VSS) U7.G9(VSSQ) U7.J2(VSS) U7.J8(VSS) U7.M1(VSS) U7.M9(VSS) U7.P1(VSS) U7.P9(VSS) U7.T1(VSS) U7.T9(VSS) U15.TPAD U19.3(GND) U33.1(A0) U33.2(A1) U33.3(A2) U33.4(VSS) U44.3(GND) U45.14(GND) U45.22(GND) U45.TPAD(PWRPAD) U64.3(GND) U66.1(GND) U70.3(GND) U74.3(GND1) U78.3(GND) U85.3(GND) U93.4(GND) U94.1(GND) U95.3(GND) U95.8(GND) X1.2(GND) Y7.2(GND) ; also on sheet 1 2 3 4 5 6 8 9 19 20 21 22 23 24 25 26 27 28 29 30 31 32 33 34
GNDPROFI: C323.2(NEG) C325.2(NEG) C430.2 C431.2 C433.2 C434.2 J14.5 L2.6 L2.7 R573.1(P1) R578.1(P1) U52.3(GND) U52.4(~{EN}) U74.9(GND2) U74.11(GND2) U74.14(GND2) U74.15(GND2) U80.2 U81.2
GNDUSB1: C557.2 C558.2 J23.S1 J23.S2 R812.1(P1)
GNDUSB2: C559.2 C560.2 J45.S1 J45.S2 J45.S3 J45.S4 R813.1(P1)
V3_3ACDCM: C320.1 C321.1 C322.1 C324.1 L3.3(OUT) U45.1(VDD2_OUT1) U45.4(VDD1_OUT0)
V3_3APCIE: C307.1 C308.1 C309.1 C310.1 C326.1 FB13.1 R546.2 R548.2 R549.2 U45.9(VDD) U45.16(VDD) U45.18(VDD) U45.20(VDD) Y7.4(VCC)
V3_3AUX_PCIE: C556.1 J22.B10 J49.2 R654.2
V3_3D: C130.1 C132.1 C133.1 C139.1 C220.1 C221.1 C319.1 C432.1 C435.1 C469.1 C470.1 FB13.2 J22.A9 J22.A10 J22.B8 J49.1 L2.2 L2.3 L3.1(IN) R149.2 R159.2(P2) R160.2(P2) R161.2(P2) R172.2(P2) R180.1(P1) R182.1(P1) R183.1(P1) R184.1(P1) R185.1(P1) R190.2 R259.2 R421.2 R422.2(P2) R423.2(P2) R434.2(P2) R435.2(P2) R436.2(P2) R437.2(P2) R438.2(P2) R439.2(P2) R440.2(P2) R441.2(P2) R442.2(P2) R443.2(P2) R444.2(P2) R445.2(P2) R446.2(P2) R447.2(P2) R448.2(P2) R449.2(P2) R450.2(P2) R543.1 R544.1 R545.2 R551.2 R649.2 R730.2(P2) R731.2(P2) R790.2 R808.2 R902.2 U15.21(VDD33_IO) U19.5(VCC) U33.8(VCC) U44.5(VCC) U70.5(VCC) U74.4(VCC1) U78.5(VCC) U85.5(VCC) X1.4(VCC) ; also on sheet 2 3 4 5 6 8 9 19 20 21 22 23 24 25 26 27 28 29 30 31 32 33 34
V3_3D_PROFIA: L2.4 U74.1(D1)
V3_3D_PROFIB: L2.1 U74.2(D2)
V3_3D_PRU2ETH0JCK: C128.1 C129.1 J6.3 J6.4 R160.1(P1)
V5_0D: U66.2(IN) U66.3(IN) U94.2(IN) U94.3(IN) ; also on sheet 4 19 21 31
V12_0D: C303.1 C304.1 J22.A2 J22.A3 J22.B1 J22.B2 J22.B3 ; also on sheet 19 21
VDDR_VREF: C44.2 C45.1 C46.1 C47.2 C53.1 C54.1 C80.2 C81.1 C82.1 C83.1 U1.Y18(DDR1_VREF) U5.H1(VREFDQ) U5.M8(VREFCA) U6.H1(VREFDQ) U6.M8(VREFCA) U7.H1(VREFDQ) U7.M8(VREFCA) ; also on sheet 9
VDDS_DDR: C29.1 C30.1 C31.1 C32.1 C33.1 C34.1 C35.1 C36.1 C37.1 C38.1 C39.1 C40.1 C41.1 C42.1 C43.1 C44.1 C47.1 C48.1 C49.1 C50.1 C51.1 C52.1 C55.1 C56.1 C57.1 C58.1 C59.1 C60.1 C61.1 C62.1 C63.1 C64.1 C65.1 C66.1 C67.1 C68.1 C69.1 C70.1 C71.1 C72.1 C73.1 C74.1 C75.1 C76.1 C77.1 C78.1 C79.1 C80.1 U5.A1(VDDQ) U5.A8(VDDQ) U5.B2(VDD) U5.C1(VDDQ) U5.C9(VDDQ) U5.D2(VDDQ) U5.D9(VDD) U5.E9(VDDQ) U5.F1(VDDQ) U5.G7(VDD) U5.H2(VDDQ) U5.H9(VDDQ) U5.K2(VDD) U5.K8(VDD) U5.N1(VDD) U5.N9(VDD) U5.R1(VDD) U5.R9(VDD) U6.A1(VDDQ) U6.A8(VDDQ) U6.B2(VDD) U6.B7(UDQSn) U6.C1(VDDQ) U6.C9(VDDQ) U6.D2(VDDQ) U6.D9(VDD) U6.E9(VDDQ) U6.F1(VDDQ) U6.G7(VDD) U6.H2(VDDQ) U6.H9(VDDQ) U6.K2(VDD) U6.K8(VDD) U6.N1(VDD) U6.N9(VDD) U6.R1(VDD) U6.R9(VDD) U7.A1(VDDQ) U7.A8(VDDQ) U7.B2(VDD) U7.C1(VDDQ) U7.C9(VDDQ) U7.D2(VDDQ) U7.D9(VDD) U7.E9(VDDQ) U7.F1(VDDQ) U7.G7(VDD) U7.H2(VDDQ) U7.H9(VDDQ) U7.K2(VDD) U7.K8(VDD) U7.N1(VDD) U7.N9(VDD) U7.R1(VDD) U7.R9(VDD) ; also on sheet 1 9 19 23
AM57XX_CLKOUT3: R905.2(P2) U1.C23(XREF_CLK3/CLKOUT3)
AM57XX_GPMC_AD0: R434.1(P1) R453.2 ; also on sheet 31
AM57XX_GPMC_AD1: R435.1(P1) R454.2 ; also on sheet 31
AM57XX_GPMC_AD2: R436.1(P1) R455.2 ; also on sheet 31
AM57XX_GPMC_AD3: R437.1(P1) R456.2 ; also on sheet 31
AM57XX_GPMC_AD4: R438.1(P1) R457.2 ; also on sheet 31
AM57XX_GPMC_AD5: R439.1(P1) R458.2 ; also on sheet 31
AM57XX_GPMC_AD6: R440.1(P1) R459.2 ; also on sheet 31
AM57XX_GPMC_AD7: R441.1(P1) R460.2 ; also on sheet 31
AM57XX_GPMC_AD8: R442.1(P1) R461.2 ; also on sheet 31
AM57XX_GPMC_AD9: R443.1(P1) R462.2 ; also on sheet 31
AM57XX_GPMC_AD10: R444.1(P1) R463.2 ; also on sheet 31
AM57XX_GPMC_AD11: R445.1(P1) R464.2 ; also on sheet 31
AM57XX_GPMC_AD12: R446.1(P1) R465.2 ; also on sheet 31
AM57XX_GPMC_AD13: R447.1(P1) R466.2 ; also on sheet 31
AM57XX_GPMC_AD14: R448.1(P1) R467.2 ; also on sheet 31
AM57XX_GPMC_AD15: R449.1(P1) R468.2 ; also on sheet 31
AM57XX_PCIE_PERn0: J22.A17 U1.AG13(PCIE_RXN0)
AM57XX_PCIE_PERp0: J22.A16 U1.AH13(PCIE_RXP0)
AM57XX_PCIE_PETn0: C477.1 U1.AG14(PCIE_TXN0)
AM57XX_PCIE_PETp0: C478.1 U1.AH14(PCIE_TXP0)
AM57XX_PCIE_REF_CLKN: C438.2 R581.1(P1) U1.AH15(LJCB_CLKN)
AM57XX_PCIE_REF_CLKP: C439.2 R581.2(P2) U1.AG15(LJCB_CLKP)
AM57XX_PR1_UART0_RXD: R575.2(P2) U1.F2(VIN2A_D0/PR1_UART0_RXD) ; also on sheet 31
AM57XX_PR1_UART0_TXD: R199.2(P2) R574.2(P2) U1.F3(VIN2A_D1/PR1_UART0_TXD) ; also on sheet 31
AM57XX_PR2_PROFI_TXEN: U1.U3(RMII50MHZCLK/PR2_GPIO) ; also on sheet 31
AM57XX_PRU2ETH0_COL: R178.2(P2) U1.F15(MCASP3_FSX/PR2_MII0_COL)
AM57XX_PRU2ETH0_CRS: R177.2(P2) U1.B18(MCASP3_ACLKX/PR2_MII0_CRS)
AM57XX_PRU2ETH0_MRCLK: R165.2(P2) U1.A13(MCASP1_AXR13/PR2_MII_MR0_CLK)
AM57XX_PRU2ETH0_RXD0: R171.2(P2) U1.C15(MCASP2_AXR2/PR2_MII0_RXD0)
AM57XX_PRU2ETH0_RXD1: R173.2(P2) U1.A18(MCASP2_FSX/PR2_MII0_RXD1)
AM57XX_PRU2ETH0_RXD2: R174.2(P2) U1.A19(MCASP2_ACLKX/PR2_MII0_RXD2)
AM57XX_PRU2ETH0_RXD3: R175.2(P2) U1.F14(MCASP1_AXR15/PR2_MII0_RXD3)
AM57XX_PRU2ETH0_RXDV: R166.2(P2) R197.2(P2) U1.G14(MCASP1_AXR14/PR2_MII0_RXDV)
AM57XX_PRU2ETH0_RXER: R170.2(P2) U1.G12(MCASP1_AXR0/PR2_MII0_RXER)
AM57XX_PRU2ETH0_RXLINK: R188.2(P2) U1.A16(MCASP2_AXR3/PR2_MII0_RXLINK)
AM57XX_PRU2ETH0_TXCLK: R162.2(P2) U1.F12(MCASP1_AXR1/PR2_MII_MT0_CLK)
AM57XX_PRU2ETH0_TXD0: R163.2(P2) U1.E14(MCASP1_AXR12/PR2_MII0_TXD0)
AM57XX_PRU2ETH0_TXD1: R164.2(P2) U1.A12(MCASP1_AXR11/PR2_MII0_TXD1)
AM57XX_PRU2ETH0_TXD2: R168.2(P2) U1.B13(MCASP1_AXR10/PR2_MII0_TXD2)
AM57XX_PRU2ETH0_TXD3: R169.2(P2) U1.A11(MCASP1_AXR9/PR2_MII0_TXD3)
AM57XX_PRU2ETH0_TXEN: R167.2(P2) R196.2(P2) U1.B12(MCASP1_AXR8/PR2_MII0_TXEN)
AM57XX_PRU2ETH_MDCLK: R179.2(P2) U1.C14(MCASP1_ACLKX/PR2_MDIO_MDCLK) ; also on sheet 27
AM57XX_PRU2ETH_MDDATA: R181.2(P2) U1.D14(MCASP1_FSX/PR2_MDIO_DATA) ; also on sheet 27
AM57XX_RTCK: R426.2 U1.E18(RTCK)
AM57XX_VIN2A_VSYNC0: R198.2(P2) ; also on sheet 31
AM57XX_VOUT1_D2: R711.2(P2) ; also on sheet 5
AM57XX_VOUT1_D3: R714.2(P2) ; also on sheet 5
AM57XX_VOUT1_D4: R715.2(P2) ; also on sheet 5
AM57XX_VOUT1_D5: R716.2(P2) ; also on sheet 5
AM57XX_VOUT1_D6: R717.2(P2) ; also on sheet 5
AM57XX_VOUT1_D7: R718.2(P2) ; also on sheet 5
AM57XX_VOUT1_D10: R712.2(P2) ; also on sheet 5
AM57XX_VOUT1_D11: R719.2(P2) ; also on sheet 5
AM57XX_VOUT1_D12: R720.2(P2) ; also on sheet 5
AM57XX_VOUT1_D13: R721.2(P2) ; also on sheet 5
AM57XX_VOUT1_D14: R722.2(P2) ; also on sheet 5
AM57XX_VOUT1_D15: R723.2(P2) ; also on sheet 5
AM57XX_VOUT1_D18: R713.2(P2) ; also on sheet 5
AM57XX_VOUT1_D19: R724.2(P2) ; also on sheet 5
AM57XX_VOUT1_D20: R725.2(P2) ; also on sheet 5
AM57XX_VOUT1_D21: R726.2(P2) ; also on sheet 5
AM57XX_VOUT1_D22: R727.2(P2) ; also on sheet 5
AM57XX_VOUT1_D23: R728.2(P2) ; also on sheet 5
AM572X_USB1_3_0_STDA_SSTX+: C555.1 U1.AD11(USB_TXP0)
AM572X_USB1_3_0_STDA_SSTX-: C554.1 U1.AC11(USB_TXN0)
AM572X_USB1_DM: L11.1 U1.AC12(USB1_DM)
AM572X_USB1_DP: L11.2 U1.AD12(USB1_DP)
AM572X_USB1_DRVVBUS: R557.2(P2) U1.AB10(USB1_DRVVBUS)
AM572X_USB2_DM: L33.2 U1.AF11(USB2_DM)
AM572X_USB2_DP: L33.1 U1.AE11(USB2_DP)
AM572X_USB2_DRVVBUS: R787.2(P2) U1.AC10(USB2_DRVVBUS)
AM572X_VIN4B_DATA0: R260.2(P2) U1.R6(GPMC_A0/VIN4B_D0)
AM572X_VIN4B_DATA1: R261.2(P2) U1.T9(GPMC_A1/VIN4B_D1)
AM572X_VIN4B_DATA2: R263.2(P2) U1.T6(GPMC_A2/VIN4B_D2)
AM572X_VIN4B_DATA3: R267.2(P2) U1.T7(GPMC_A3/VIN4B_D3)
AM572X_VIN4B_DATA4: R269.2(P2) U1.P6(GPMC_A4/VIN4B_D4)
AM572X_VIN4B_DATA5: R271.2(P2) U1.R9(GPMC_A5/VIN4B_D5)
AM572X_VIN4B_DATA6: R262.1(P1) U1.R5(GPMC_A6/VIN4B_D6)
AM572X_VIN4B_DATA7: R264.1(P1) U1.P5(GPMC_A7/VIN4B_D7)
AM572X_VIN4B_DE: R273.2(P2) U1.P9(GPMC_A11/VIN4B_DE1)
AM572X_VIN4B_FLD: R274.1(P1) U1.P4(GPMC_A12/VIN4B_FLD1)
AM572X_VIN4B_HSYNC: R258.1(P1) U1.N7(GPMC_A8/VIN4B_HSYNC1)
AM572X_VIN4B_PCLK: R265.2(P2) U1.N9(GPMC_A10/VIN4B_CLK1)
AM572X_VIN4B_VSYNC: R257.1(P1) U1.R4(GPMC_A9/VIN4B_VSYNC1)
CAM1_DATA0: J9.3 R260.1(P1)
CAM1_DATA1: J9.5 R261.1(P1)
CAM1_DATA2: J9.7 R263.1(P1)
CAM1_DATA3: J9.13 R267.1(P1)
CAM1_DATA4: J9.15 R269.1(P1)
CAM1_DATA5: J9.17 R271.1(P1)
CAM1_DATA6: J9.6 R262.2(P2)
CAM1_DATA7: J9.8 R264.2(P2)
CAM1_FIELD: J9.20 R274.2(P2)
CAM1_GIO0: J9.16 R259.1
CAM1_HSYNC: J9.4 R258.2(P2)
CAM1_PCLK: J9.9 R265.1(P1)
CAM1_VSYNC: J9.2 R257.2(P2)
CAM1_WEN: J9.19 R273.1(P1)
CAM_ENn: J9.18 ; also on sheet 31
DDR_A0: U1.AD20(DDR1_A0) U5.N3(A0) U6.N3(A0) U7.N3(A0) ; also on sheet 9
DDR_A1: U1.AC19(DDR1_A1) U5.P7(A1) U6.P7(A1) U7.P7(A1) ; also on sheet 9
DDR_A2: U1.AC20(DDR1_A2) U5.P3(A2) U6.P3(A2) U7.P3(A2) ; also on sheet 9
DDR_A3: U1.AB19(DDR1_A3) U5.N2(A3) U6.N2(A3) U7.N2(A3) ; also on sheet 9
DDR_A4: U1.AF21(DDR1_A4) U5.P8(A4) U6.P8(A4) U7.P8(A4) ; also on sheet 9
DDR_A5: U1.AH22(DDR1_A5) U5.P2(A5) U6.P2(A5) U7.P2(A5) ; also on sheet 9
DDR_A6: U1.AG23(DDR1_A6) U5.R8(A6) U6.R8(A6) U7.R8(A6) ; also on sheet 9
DDR_A7: U1.AE21(DDR1_A7) U5.R2(A7) U6.R2(A7) U7.R2(A7) ; also on sheet 9
DDR_A8: U1.AF22(DDR1_A8) U5.T8(A8) U6.T8(A8) U7.T8(A8) ; also on sheet 9
DDR_A9: U1.AE22(DDR1_A9) U5.R3(A9) U6.R3(A9) U7.R3(A9) ; also on sheet 9
DDR_A10: U1.AD21(DDR1_A10) U5.L7(A10/AP) U6.L7(A10/AP) U7.L7(A10/AP) ; also on sheet 9
DDR_A11: U1.AD22(DDR1_A11) U5.R7(A11) U6.R7(A11) U7.R7(A11) ; also on sheet 9
DDR_A12: U1.AC21(DDR1_A12) U5.N7(A12/~{BC}) U6.N7(A12/~{BC}) U7.N7(A12/~{BC}) ; also on sheet 9
DDR_A13: U1.AF18(DDR1_A13) U5.T3(A13) U6.T3(A13) U7.T3(A13) ; also on sheet 9
DDR_A14: U1.AE17(DDR1_A14) U5.T7(A14) U6.T7(A14) U7.T7(A14) ; also on sheet 9
DDR_A15: U1.AD18(DDR1_A15) U5.M7(NU4) U6.M7(NU4) U7.M7(NU4) ; also on sheet 9
DDR_BA0: U1.AF17(DDR1_BA0) U5.M2(BA0) U6.M2(BA0) U7.M2(BA0) ; also on sheet 9
DDR_BA1: U1.AE18(DDR1_BA1) U5.N8(BA1) U6.N8(BA1) U7.N8(BA1) ; also on sheet 9
DDR_BA2: U1.AB18(DDR1_BA2) U5.M3(BA2) U6.M3(BA2) U7.M3(BA2) ; also on sheet 9
DDR_CASn: U1.AC18(DDR1_CASn) U5.K3(CASn) U6.K3(CASn) U7.K3(CASn) ; also on sheet 9
DDR_CKE: U1.AG22(DDR1_CKE) U5.K9(CKE) U6.K9(CKE) U7.K9(CKE) ; also on sheet 9
DDR_CLK: U1.AG24(DDR1_CK) U5.J7(CK) U6.J7(CK) U7.J7(CK) ; also on sheet 9
DDR_CLKn: U1.AH24(DDR1_CKn) U5.K7(CKn) U6.K7(CKn) U7.K7(CKn) ; also on sheet 9
DDR_CS0n: U1.AH23(DDR1_CSN0) U5.L2(CSn) U6.L2(CSn) U7.L2(CSn) ; also on sheet 9
DDR_D0: U1.AF25(DDR1_D0) U5.E3(DQ0)
DDR_D1: U1.AF26(DDR1_D1) U5.F7(DQ1)
DDR_D2: U1.AG26(DDR1_D2) U5.F8(DQ3)
DDR_D3: U1.AH26(DDR1_D3) U5.H8(DQ5)
DDR_D4: U1.AF24(DDR1_D4) U5.F2(DQ2)
DDR_D5: U1.AE24(DDR1_D5) U5.G2(DQ6)
DDR_D6: U1.AF23(DDR1_D6) U5.H3(DQ4)
DDR_D7: U1.AE23(DDR1_D7) U5.H7(DQ7)
DDR_D8: U1.AC23(DDR1_D8) U5.D7(DQ8)
DDR_D9: U1.AF27(DDR1_D9) U5.C3(DQ9)
DDR_D10: U1.AG27(DDR1_D10) U5.A3(DQ15)
DDR_D11: U1.AF28(DDR1_D11) U5.A7(DQ12)
DDR_D12: U1.AE26(DDR1_D12) U5.A2(DQ13)
DDR_D13: U1.AC25(DDR1_D13) U5.C8(DQ10)
DDR_D14: U1.AC24(DDR1_D14) U5.B8(DQ14)
DDR_D15: U1.AD25(DDR1_D15) U5.C2(DQ11)
DDR_D16: U1.V20(DDR1_D16) U7.E3(DQ0)
DDR_D17: U1.W20(DDR1_D17) U7.H8(DQ5)
DDR_D18: U1.AB28(DDR1_D18) U7.H3(DQ4)
DDR_D19: U1.AC28(DDR1_D19) U7.G2(DQ6)
DDR_D20: U1.AC27(DDR1_D20) U7.F2(DQ2)
DDR_D21: U1.Y19(DDR1_D21) U7.F7(DQ1)
DDR_D22: U1.AB27(DDR1_D22) U7.H7(DQ7)
DDR_D23: U1.Y20(DDR1_D23) U7.F8(DQ3)
DDR_D24: U1.AA23(DDR1_D24) U7.D7(DQ8)
DDR_D25: U1.Y22(DDR1_D25) U7.C3(DQ9)
DDR_D26: U1.Y23(DDR1_D26) U7.B8(DQ14)
DDR_D27: U1.AA24(DDR1_D27) U7.A2(DQ13)
DDR_D28: U1.Y24(DDR1_D28) U7.C2(DQ11)
DDR_D29: U1.AA26(DDR1_D29) U7.A7(DQ12)
DDR_D30: U1.AA25(DDR1_D30) U7.C8(DQ10)
DDR_D31: U1.AA28(DDR1_D31) U7.A3(DQ15)
DDR_DQM0: U1.AD23(DDR1_DQM0) U5.E7(LDM)
DDR_DQM1: U1.AB23(DDR1_DQM1) U5.D3(UDM)
DDR_DQM2: U1.AC26(DDR1_DQM2) U7.E7(LDM)
DDR_DQM3: U1.AA27(DDR1_DQM3) U7.D3(UDM)
DDR_DQS0: U1.AH25(DDR1_DQS0) U5.F3(LDQS)
DDR_DQS1: U1.AE27(DDR1_DQS1) U5.C7(UDQS)
DDR_DQS2: U1.AD27(DDR1_DQS2) U7.F3(LDQS)
DDR_DQS3: U1.Y28(DDR1_DQS3) U7.C7(UDQS)
DDR_DQSn0: U1.AG25(DDR1_DQS0n) U5.G3(LDQSn)
DDR_DQSn1: U1.AE28(DDR1_DQS1n) U5.B7(UDQSn)
DDR_DQSn2: U1.AD28(DDR1_DQS2n) U7.G3(LDQSn)
DDR_DQSn3: U1.Y27(DDR1_DQS3n) U7.B7(UDQSn)
DDR_ODT: U1.AE20(DDR1_ODT0) U5.K1(ODT) U6.K1(ODT) U7.K1(ODT) ; also on sheet 9
DDR_RASn: U1.AF20(DDR1_RASn) U5.J3(RASn) U6.J3(RASn) U7.J3(RASn) ; also on sheet 9
DDR_RESETn: U1.AG21(DDR1_RST) U5.T2(RESETn) U6.T2(RESETn) U7.T2(RESETn) ; also on sheet 9
DDR_WEn: U1.AH21(DDR1_WEn) U5.L3(WEn) U6.L3(WEn) U7.L3(WEn) ; also on sheet 9
DDRECC_D0: U1.W22(DDR1_ECC_D0) U6.E3(DQ0)
DDRECC_D1: U1.V23(DDR1_ECC_D1) U6.F7(DQ1)
DDRECC_D2: U1.W19(DDR1_ECC_D2) U6.H8(DQ5)
DDRECC_D3: U1.W23(DDR1_ECC_D3) U6.F8(DQ3)
DDRECC_D4: U1.Y25(DDR1_ECC_D4) U6.F2(DQ2)
DDRECC_D5: U1.V24(DDR1_ECC_D5) U6.H7(DQ7)
DDRECC_D6: U1.V25(DDR1_ECC_D6) U6.H3(DQ4)
DDRECC_D7: U1.Y26(DDR1_ECC_D7) U6.G2(DQ6)
DDRECC_DQM: U1.V26(DDR1_ECC_DQM) U6.E7(LDM)
DDRECC_DQS: U1.V27(DDR1_ECC_DQS) U6.F3(LDQS)
DDRECC_DQSn: U1.V28(DDR1_ECC_DQSn) U6.G3(LDQSn)
EMU2: J18.13(TR_CLK0) R711.1(P1)
EMU3: J18.17(TRD0.0) R712.1(P1)
EMU4: J18.23(TRD0.3) R713.1(P1)
EMU5: J18.25(TRD0.4) R714.1(P1)
EMU6: J18.27(TRD0.5) R715.1(P1)
EMU7: J18.29(TRD0.6) R716.1(P1)
EMU8: J18.31(TRD0.7) R717.1(P1)
EMU9: J18.33(TRD0.8) R718.1(P1)
EMU10: J18.35(TRD0.9) R719.1(P1)
EMU11: J18.37(TRD3.0) R720.1(P1)
EMU12: J18.39(TRD3.1) R721.1(P1)
EMU13: J18.41(TRD3.2) R722.1(P1)
EMU14: J18.43(TRD3.3) R723.1(P1)
EMU15: J18.45(TRD3.4) R724.1(P1)
EMU16: J18.47(TRD3.5) R725.1(P1)
EMU17: J18.49(TRD3.6) R726.1(P1)
EMU18: J18.51(TRD3.7) R727.1(P1)
EMU19: J18.53(TRD3.8) R728.1(P1)
EMU_RSTn: C223.1 J18.6(RESETn) R429.2(P2) R450.1(P1)
GPIO_AM572X_USB2_ID: R788.2(P2) U1.AF2(VIN1A_D12/GPIO)
GPIO_PCIE_RSTDRVn: U44.1(~{OE}) ; also on sheet 31
GPIO_PCIE_SWRSTn: U85.2(B) ; also on sheet 31
GPIO_PRU2_ETH0_RESETn: R195.2(P2) ; also on sheet 31
HDQ: R300.1(P1) ; also on sheet 31
IND_I2C_SCL: R275.1(P1) R652.2(P2) U33.6(SCL) ; also on sheet 5 20 21 26 31
IND_I2C_SDA: R277.1(P1) R653.2(P2) U33.5(SDA) ; also on sheet 5 20 21 26 31
JTAG_EMU0: J18.19(TRD0.1) R422.1(P1) U1.G21(EMU0) ; also on sheet 2
JTAG_EMU1: J18.21(TRD0.2) R423.1(P1) U1.D24(EMU1) ; also on sheet 2
JTAG_TCK: R3.2 U1.E20(TCK) ; also on sheet 2
JTAG_TDI: J18.5(TDI) U1.D23(TDI) ; also on sheet 2
JTAG_TDO: J18.4(TDO) U1.F19(TDO) ; also on sheet 2
JTAG_TMS: J18.2(TMS) U1.F18(TMS) ; also on sheet 2
JTAG_TRSTn: J18.8(TRSTPD) R433.2(P2) U1.D20(TRSTn) ; also on sheet 2
JTAGPOD_PRES: U19.4(Y) ; also on sheet 2
PCI_CONN_REFN: C436.1 U45.5(OUT0N)
PCI_CONN_REFP: C437.1 U45.6(OUT0P)
PCIE_CRDPRESENT: R650.1(P1) ; also on sheet 31
PCIE_PERSTn: J22.A11 R545.1 U44.4(Y)
PCIE_REFCLKN: C436.2 J22.A14 R580.2(P2)
PCIE_REFCLKP: C437.2 J22.A13 R580.1(P1)
PCIE_RESETn: R568.2(P2) U85.1(A) ; also on sheet 32
PCIE_SMB_CLK: J22.B5 R652.1(P1)
PCIE_SMB_DATA: J22.B6 R653.1(P1)
PCIE_TCK: J22.A5 R542.2
PCIE_TDI: J22.A6 R543.2
PCIE_TDO: J22.A7 TP20.1
PCIE_TMS: J22.A8 R544.2
PCIE_TRSTn: J22.B9 R539.2
PCIE_WAKEn: R655.1(P1) ; also on sheet 31
PCIECONN_PETn0: C477.2 J22.B15
PCIECONN_PETp0: C478.2 J22.B14
PHY_RESETn: U70.2(B) ; also on sheet 22 24 26 27 28 32
PR1_EDIO_DATA_OUT4: J7.3 R198.1(P1)
PR1_EDIO_DATA_OUT6: J7.4 R199.1(P1)
PR2_MII0_RXDV: J7.2 R197.1(P1)
PR2_MII0_TXEN: J7.1 R196.1(P1)
PROFIBUS_A: J14.3 R577.1(P1) U74.12(A) U81.1
PROFIBUS_B: J14.8 R578.2(P2) U74.13(B) U80.1
PRU2ETH0_25MHzCLK: U15.23(XI) ; also on sheet 28
PRU2ETH0_COL: R187.2(P2) R188.1(P1) R189.2(P2) U15.29(COL)
PRU2ETH0_CRS: R177.1(P1) U15.27(CRS)
PRU2ETH0_INTn: U15.8(PWRDNn/INTn) ; also on sheet 31
PRU2ETH0_LINKLED: R159.1(P1) R176.2(P2) U15.17(LED_LINK)
PRU2ETH0_MDC: R179.1(P1) U15.20(MDC)
PRU2ETH0_MDIO: R181.1(P1) U15.19(MDIO)
PRU2ETH0_RESETn: U15.18(RESET_N) U70.4(Y)
PRU2ETH0_RXCLK: R165.1(P1) U15.25(RX_CLK)
PRU2ETH0_RXD0: R171.1(P1) R194.2(P2) U15.30(RXD_0)
PRU2ETH0_RXD1: R173.1(P1) R193.2(P2) U15.31(RXD_1)
PRU2ETH0_RXD2: R174.1(P1) R192.2(P2) U15.32(RXD_2)
PRU2ETH0_RXD3: R175.1(P1) R191.2(P2) U15.1(RXD_3)
PRU2ETH0_RXDV: R166.1(P1) U15.26(RX_DV)
PRU2ETH0_RXERR: R170.1(P1) U15.28(RX_ERR)
PRU2ETH0_TXCLK: R162.1(P1) U15.2(TX_CLK)
PRU2ETH0_TXD0: R163.1(P1) U15.4(TXD_0)
PRU2ETH0_TXD1: R164.1(P1) U15.5(TXD_1)
PRU2ETH0_TXD2: R168.1(P1) U15.6(TXD_2)
PRU2ETH0_TXD3: R169.1(P1) U15.7(TXD_3)
PRU2ETH0_TXEN: R167.1(P1) U15.3(TX_EN)
PRU2ETHER0_RDN: J6.2 R182.2(P2) U15.9(RD-)
PRU2ETHER0_RDP: J6.1 R183.2(P2) U15.10(RD+)
PRU2ETHER0_TDN: J6.6 R184.2(P2) U15.11(TD-)
PRU2ETHER0_TDP: J6.5 R185.2(P2) U15.12(TD+)
RTCK: J18.7(RTCK) R426.1
SERDES_REF_CLKN: C438.1 U45.2(OUT1N)
SERDES_REF_CLKP: C439.1 U45.3(OUT1P)
SRCCLK: R276.1 ; also on sheet 5
SYS_WARMRESETn: U78.4(Y) ; also on sheet 2 32
TCK: J18.3(TCK) R3.1
USB1_3_0_STDA_SSRX+: J23.6(STDA_SSRX+) U1.AE12(USB_RXP0) U95.2(D1-)
USB1_3_0_STDA_SSRX-: J23.5(STDA_SSRX-) U1.AF12(USB_RXN0) U95.1(D1+)
USB1_3_0_STDA_SSTX+: C555.2 J23.9(STDA_SSTX+) U95.5(D2-)
USB1_3_0_STDA_SSTX-: C554.2 J23.8(STDA_SSTX-) U95.4(D2+)
USB1_CONN_DM: J23.2(DM) L11.4 U64.2(D-)
USB1_CONN_DP: J23.3(DP) L11.3 U64.1(D+)
USB1_OVRCURn: R551.1 U66.5(~{OC})
USB1_VBUS_EN: R553.1 R557.1(P1) U66.4(EN)
USB2_CONN_DM: J45.2(DM) L33.3 U93.2(D-)
USB2_CONN_DP: J45.3(DP) L33.4 U93.1(D+)
USB2_ID: J45.4(ID) R788.1(P1) R808.1 U93.3(ID)
USB2_OVRCURn: R790.1 U94.5(~{OC})
USB2_VBUS_EN: R787.1(P1) R791.1 U94.4(EN)
VADD33_PRU2ETH0: C137.1 R180.2(P2) U15.14(AVDD33)
VMAIN: C152.1 J9.1 ; also on sheet 5 19 20 31
VPROFI: C323.1(POS) C325.1(POS) C430.1 C431.1 J14.6 R577.2(P2) U52.7(OUT) U52.8(OUT) U74.16(VCC2)
VPROFI_SRC: C433.1 C434.1 D14.1(CATHODE) D15.1(CATHODE) U52.5(IN) U52.6(IN)
VPROFI_TRANSA: D15.2(ANODE) L2.8
VPROFI_TRANSB: D14.2(ANODE) L2.5
VUSB_VBUS1: C311.1 J23.1(VBUS) U66.6(OUT) U66.7(OUT) U66.8(OUT)
VUSB_VBUS2: C546.1 C547.1 J45.1(VBUS) J50.2 U93.6(VBUS) U94.6(OUT) U94.7(OUT) U94.8(OUT) ; also on sheet 20
N17594977: C134.1 C135.1 C136.1 C138.1 U15.13(PFBIN1) U15.15(PFBOUT) U15.24(PFBIN2)
N17595008: J6.9 R172.1(P1)
N17595032: R190.1 R195.1(P1) U70.1(A)
N17595048: R186.2(P2) U15.16(RBIAS)
N17595072: J6.10 R189.1(P1)
N17595076: J6.11 R161.1(P1)
N17595078: J6.12 R176.1(P1)
N17745676: J9.22 R275.2(P2)
N17745678: J9.24 R277.2(P2)
N17745710: J9.23 R903.1
N19120663: R41.2(P2) U5.L8(ZQ)
N19120749: R44.2(P2) U7.L8(ZQ)
N19127709: R42.2(P2) U6.L8(ZQ)
N19139994: R32.1 U6.D7(DQ8)
N19139997: R33.1 U6.C3(DQ9)
N19140025: R34.1 U6.C8(DQ10)
N19140027: R35.1 U6.C2(DQ11)
N19140065: R37.1 U6.A7(DQ12)
N19140067: R38.1 U6.A2(DQ13)
N19140105: R39.1 U6.B8(DQ14)
N19140107: R40.1 U6.A3(DQ15)
N19258097: R546.1 U45.7(OE)
N19258128: U45.21(XIN) Y7.3(CLK)
N19258198: R547.1(P1) Y7.1(OE)
N19258383: R548.1 U45.11(OS0)
N19258403: R549.1 R550.1(P1) U45.10(OS1)
N19258622: C305.1 U45.17(REG_CAP2)
N19258627: C306.1 U45.19(REG_CAP1)
N19290398: R421.1 U33.7(WP)
N19415733: R568.1(P1) U45.12(RSTn)
N19634423: R579.2(P2) U74.6(~{RE})
N19634430: R574.1(P1) U74.8(D)
N19634431: R575.1(P1) U74.5(R)
N19634433: R576.1(P1) U74.7(DE)
N19700674: J18.1(VREF_DBG) R730.1(P1)
N19700725: J18.12(VREF_TR) R731.1(P1)
N19707292: J18.15(TGT_DETECT) R587.1(P1)
N19708748: R429.1(P1) U78.2(A)
N20301491: J22.A1 R649.1 R650.2(P2)
N20338433: J22.B11 R654.1 R655.2(P2)
N20537306: U44.2(A) U85.4(Y)
N20962931: C421.1 J18.58(GND) R149.1 U19.2(A)
N21605448: C545.1 J50.1
N22642197: R276.2 R300.2(P2) R903.2 R905.1(P1) X1.3(OUT)
N22691021: R576.2(P2) U1.F4(VIN2A_D5/PR1_PRU1_R30_2)
N24440306: R902.1 X1.1(EN)

Not connected (* = marked no-connect by the designer): J6 7*; J9 10* 14*; J14 1* 2* 4* 7* 9*; J18 9(TRSTn)* 10(EXTE)* 11(EXTF)* 14(TR_CLK1)* 18(TRD1.0)* 20(TRD1.1)* 22(TRD1.2)* 24(TRD1.3)* 26(TRD1.4)* 28(TRD1.5)* 30(TRD1.6)* 32(TRD1.7)* 34(TRD1.8)* 36(TRD1.9)* 38(TRD2.0)* 40(TRD2.1)* 42(TRD2.2)* 44(TRD2.3)* 46(TRD2.4)* 48(TRD2.5)* 50(TRD2.6)* 52(TRD2.7)* 54(TRD2.8)* 55(TRD3.9)* 56(TRD2.9)* 59(TR_CLK3)* 60(TR_CLK2)*; J22 B12*; R178 1(P1)*; U5 J1(NU0) J9(NU1) L1(NU2) L9(NU3); U6 J1(NU0) J9(NU1) L1(NU2) L9(NU3); U7 J1(NU0) J9(NU1) L1(NU2) L9(NU3); U15 22(XO)*; U19 1(NC)*; U45 8(NC8)* 13(NC13)* 15(NC15)* 23(OSCOUT)* 24(NC24)* 25(NC25)* 26(NC26)* 27(NC27)* 28(NC28)* 29(NC29)* 30(NC30)* 31(NC31)* 32(NC32)*; U52 1(NC/FB)* 2(PG)*; U74 10(ISODE)*; U78 1(NC)*; U93 5(NC); U95 6(NC6)* 7(NC7)* 9(NC9)* 10(NC10)*

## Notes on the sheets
sheet 10
- ID Memory
- JTAG Connector
- Boot Configuration
sheet 13
- AM574x Industrial Development Kit
sheet 14
- USB2 Port
sheet 15
- USB1 Port
sheet 16
- Note that ECC use is
  highly constrained -
  please refer to the
  AM572x Errata document
  for more information
sheet 17
- Note: MDIO Address = 0x00
- Real-Time Development
  Header
